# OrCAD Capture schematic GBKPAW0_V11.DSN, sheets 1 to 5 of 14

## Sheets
1 PAGE07:LCD PORT: size B; title: GBKPAW0_V1.1; rev: 1.1; note: 研发部
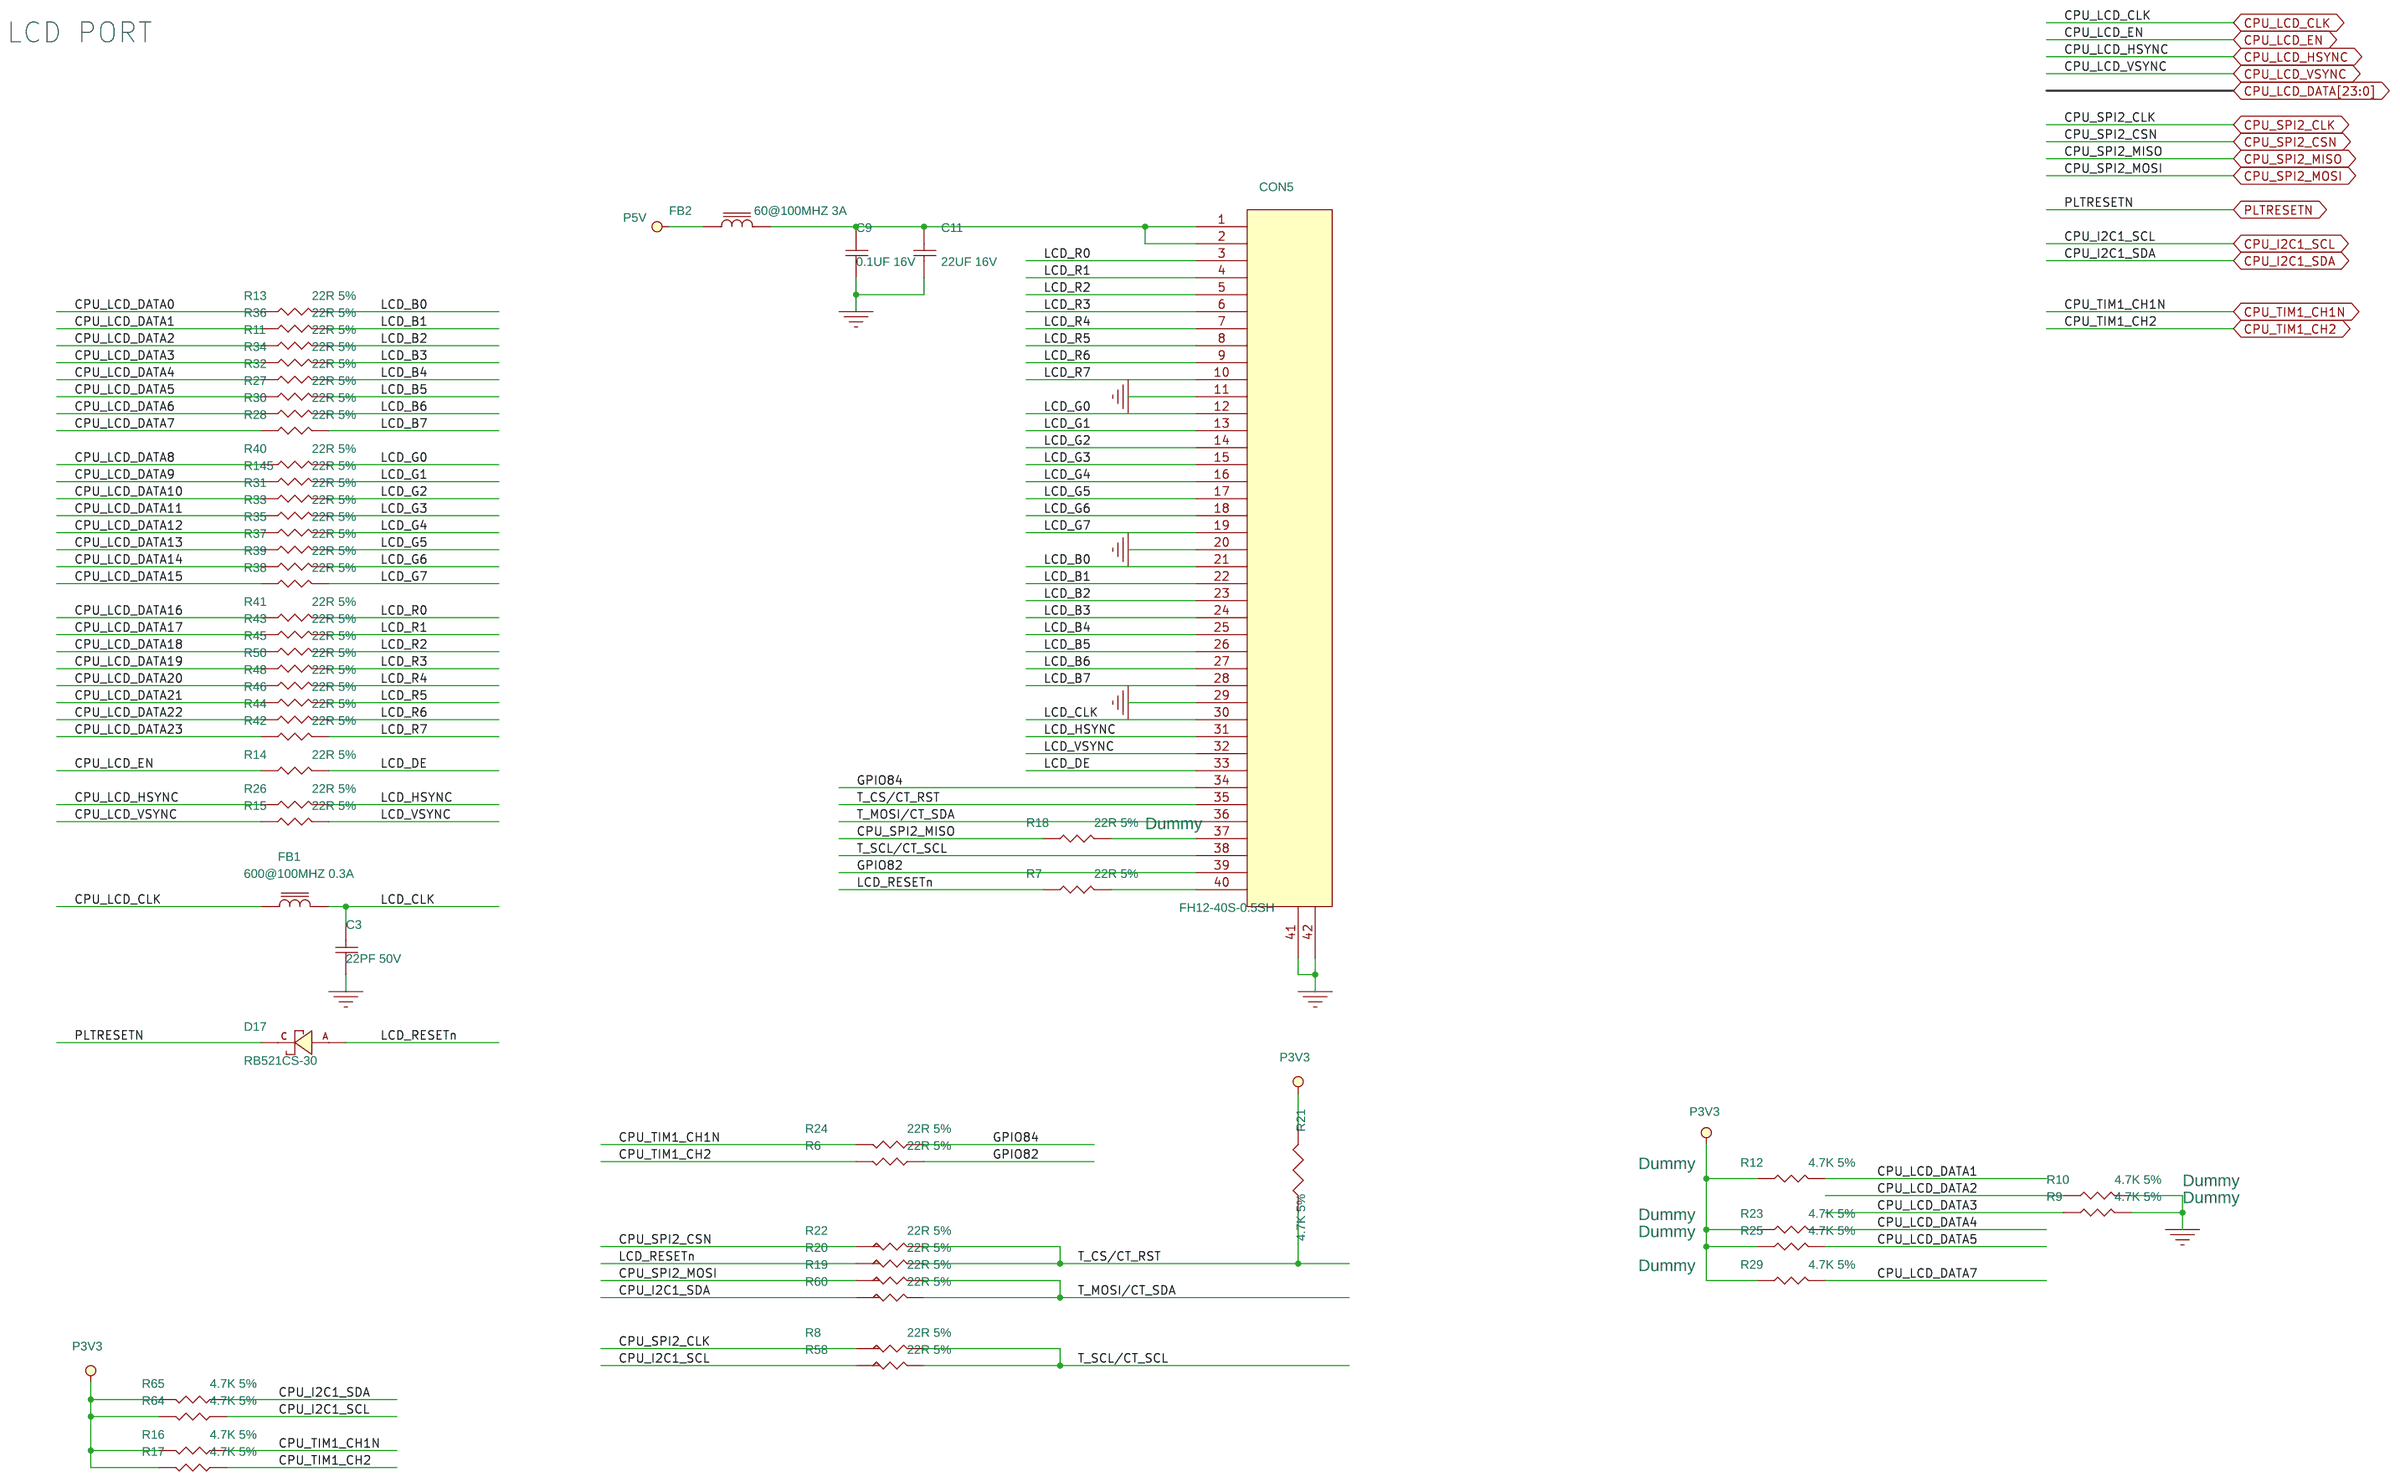
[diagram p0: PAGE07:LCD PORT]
2 PAGE13:P3V3: size B
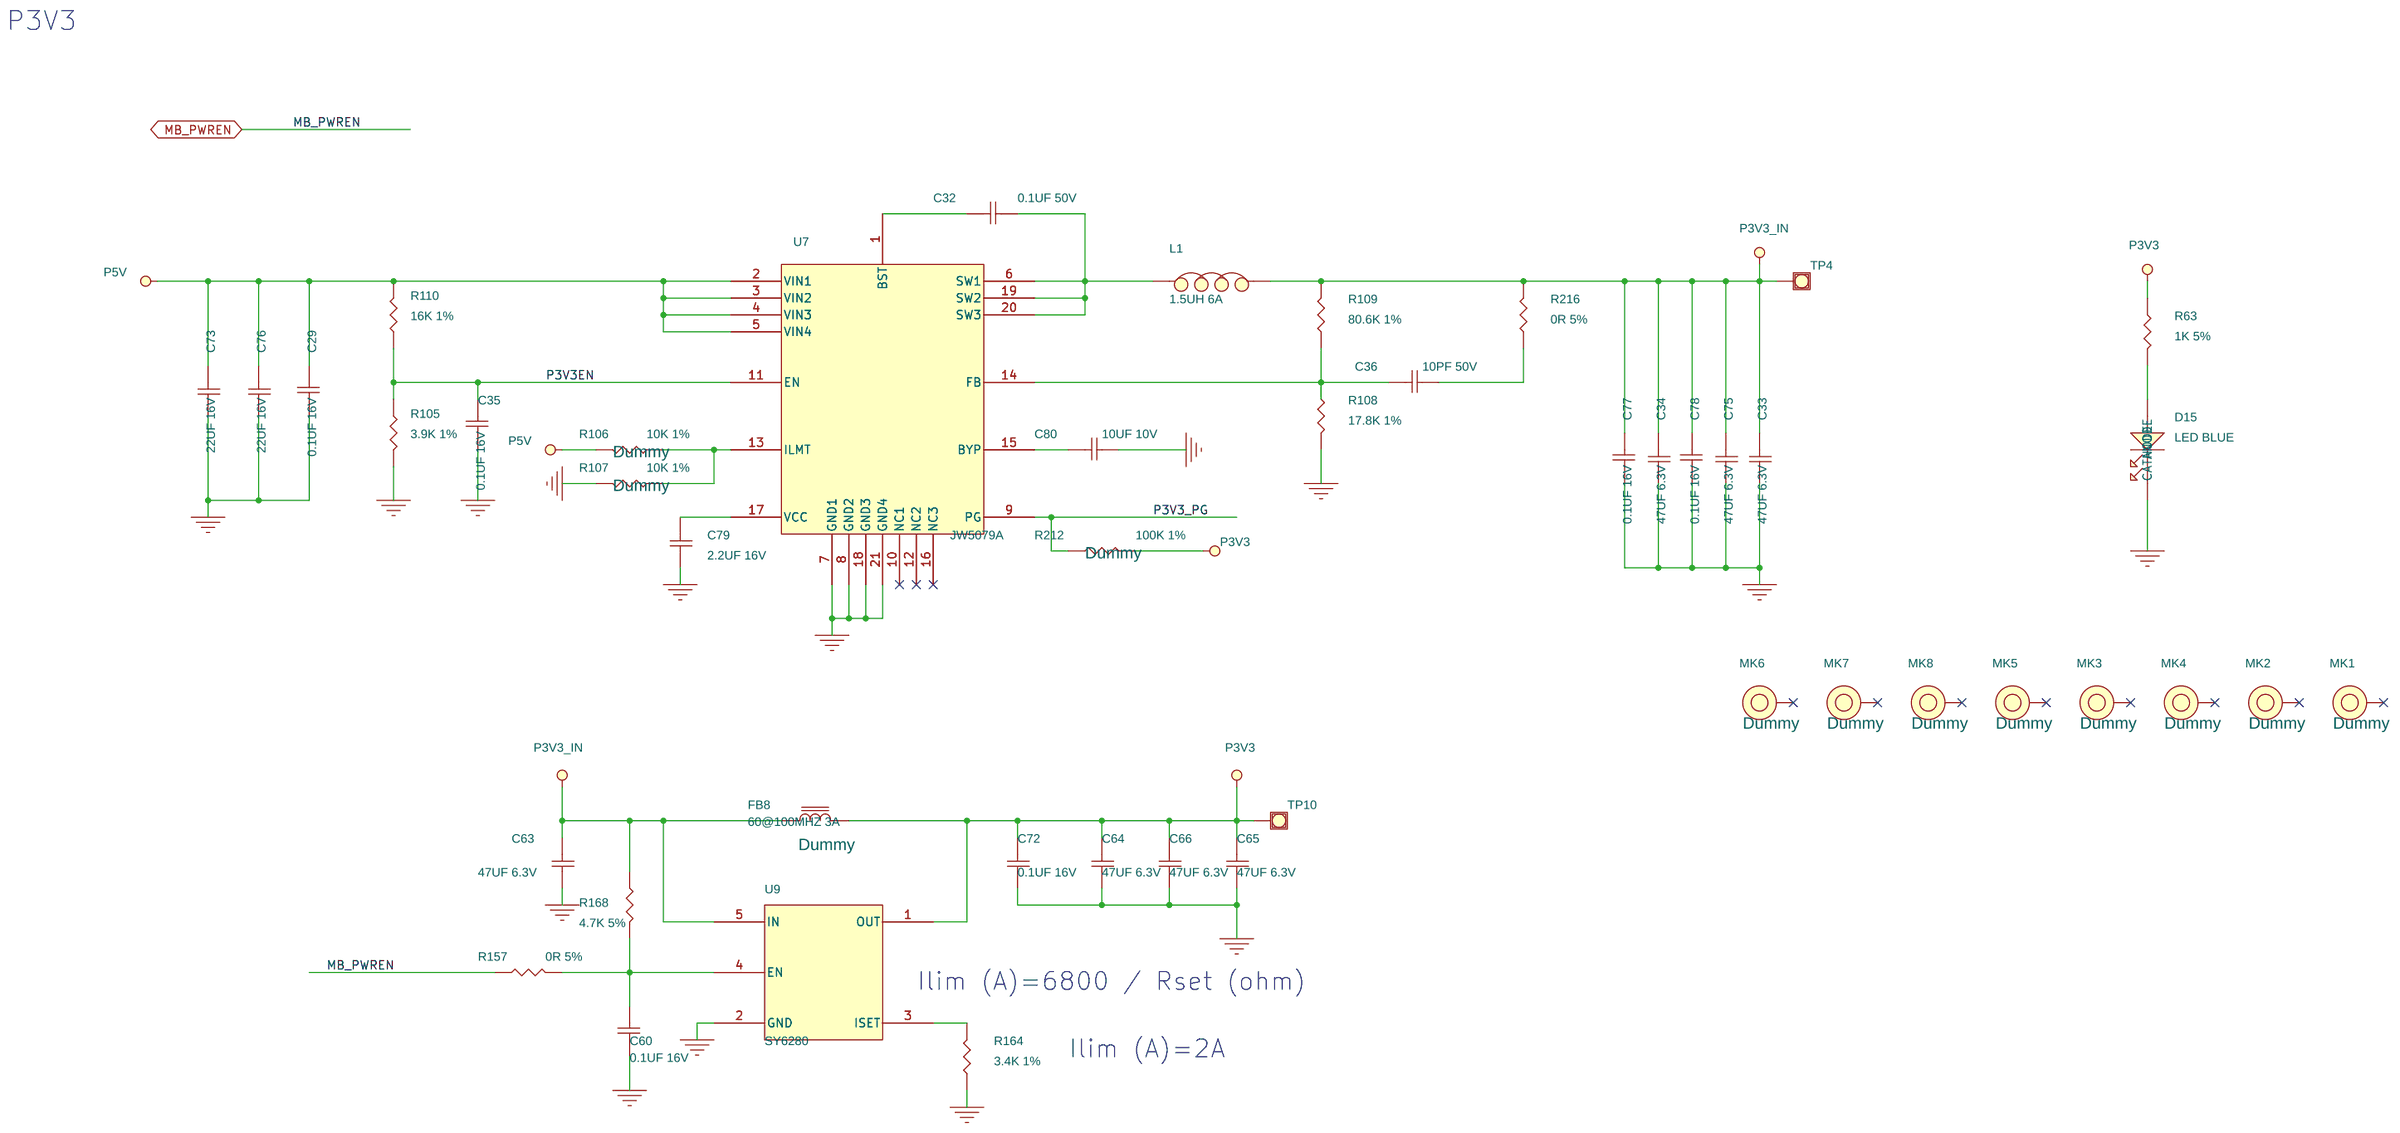
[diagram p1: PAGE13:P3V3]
3 PAGE05:USB: size B
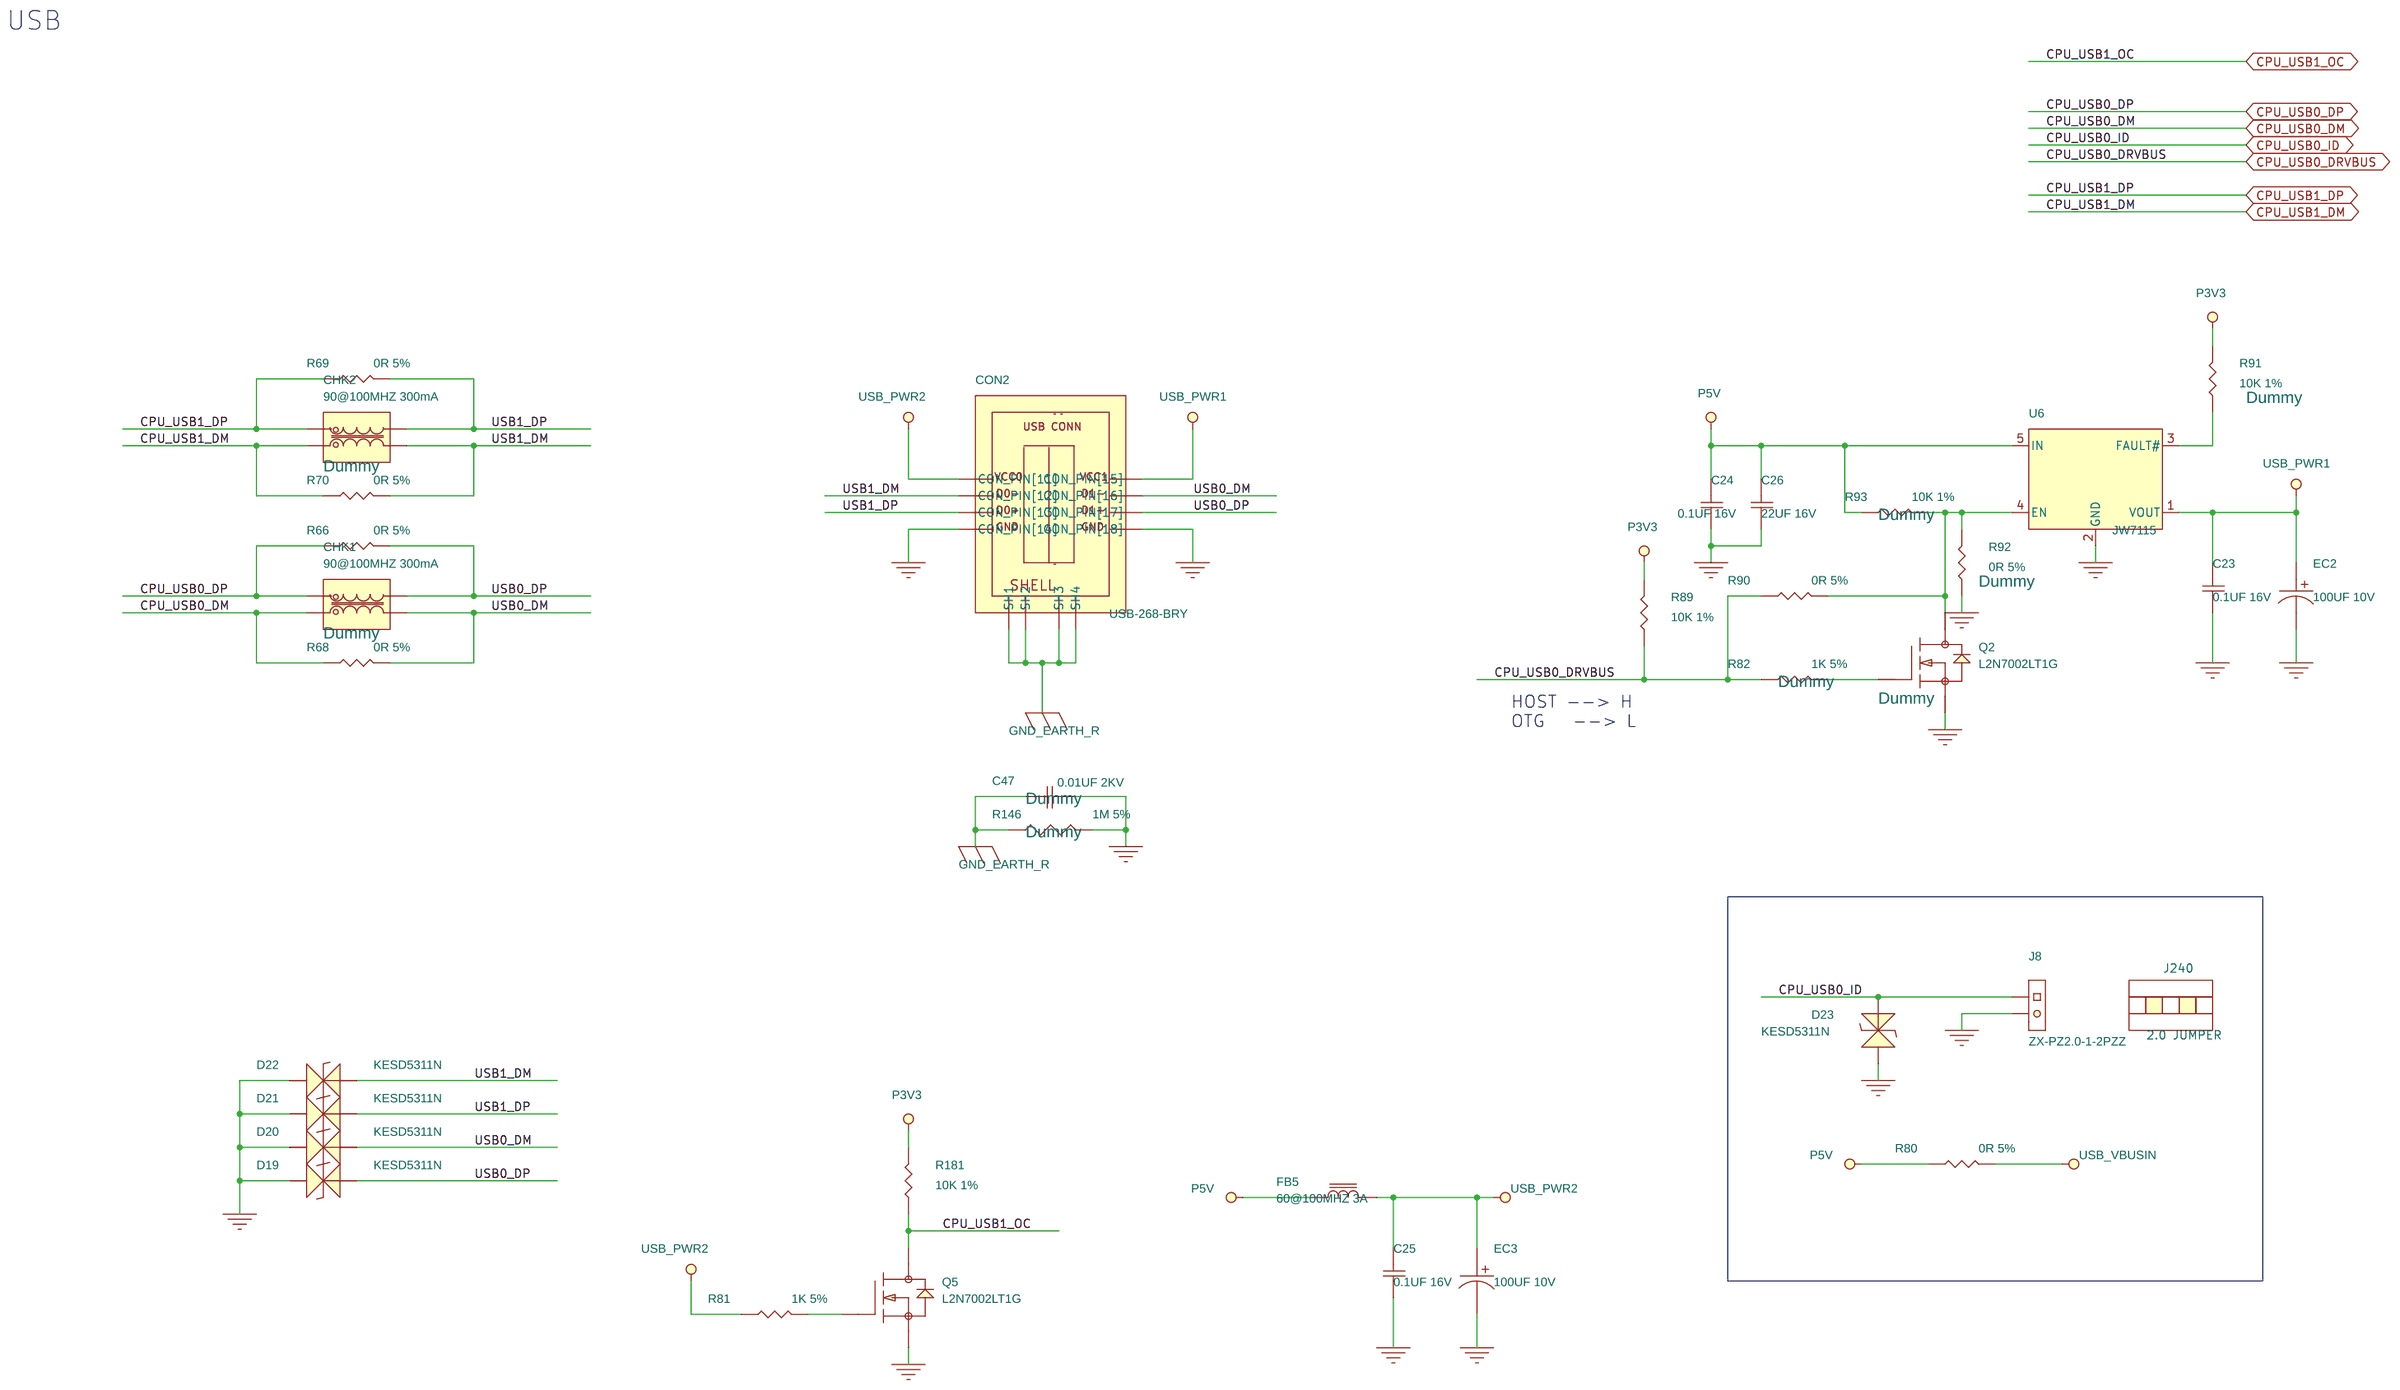
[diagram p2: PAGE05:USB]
4 PAGE09:AI&LAN: size B
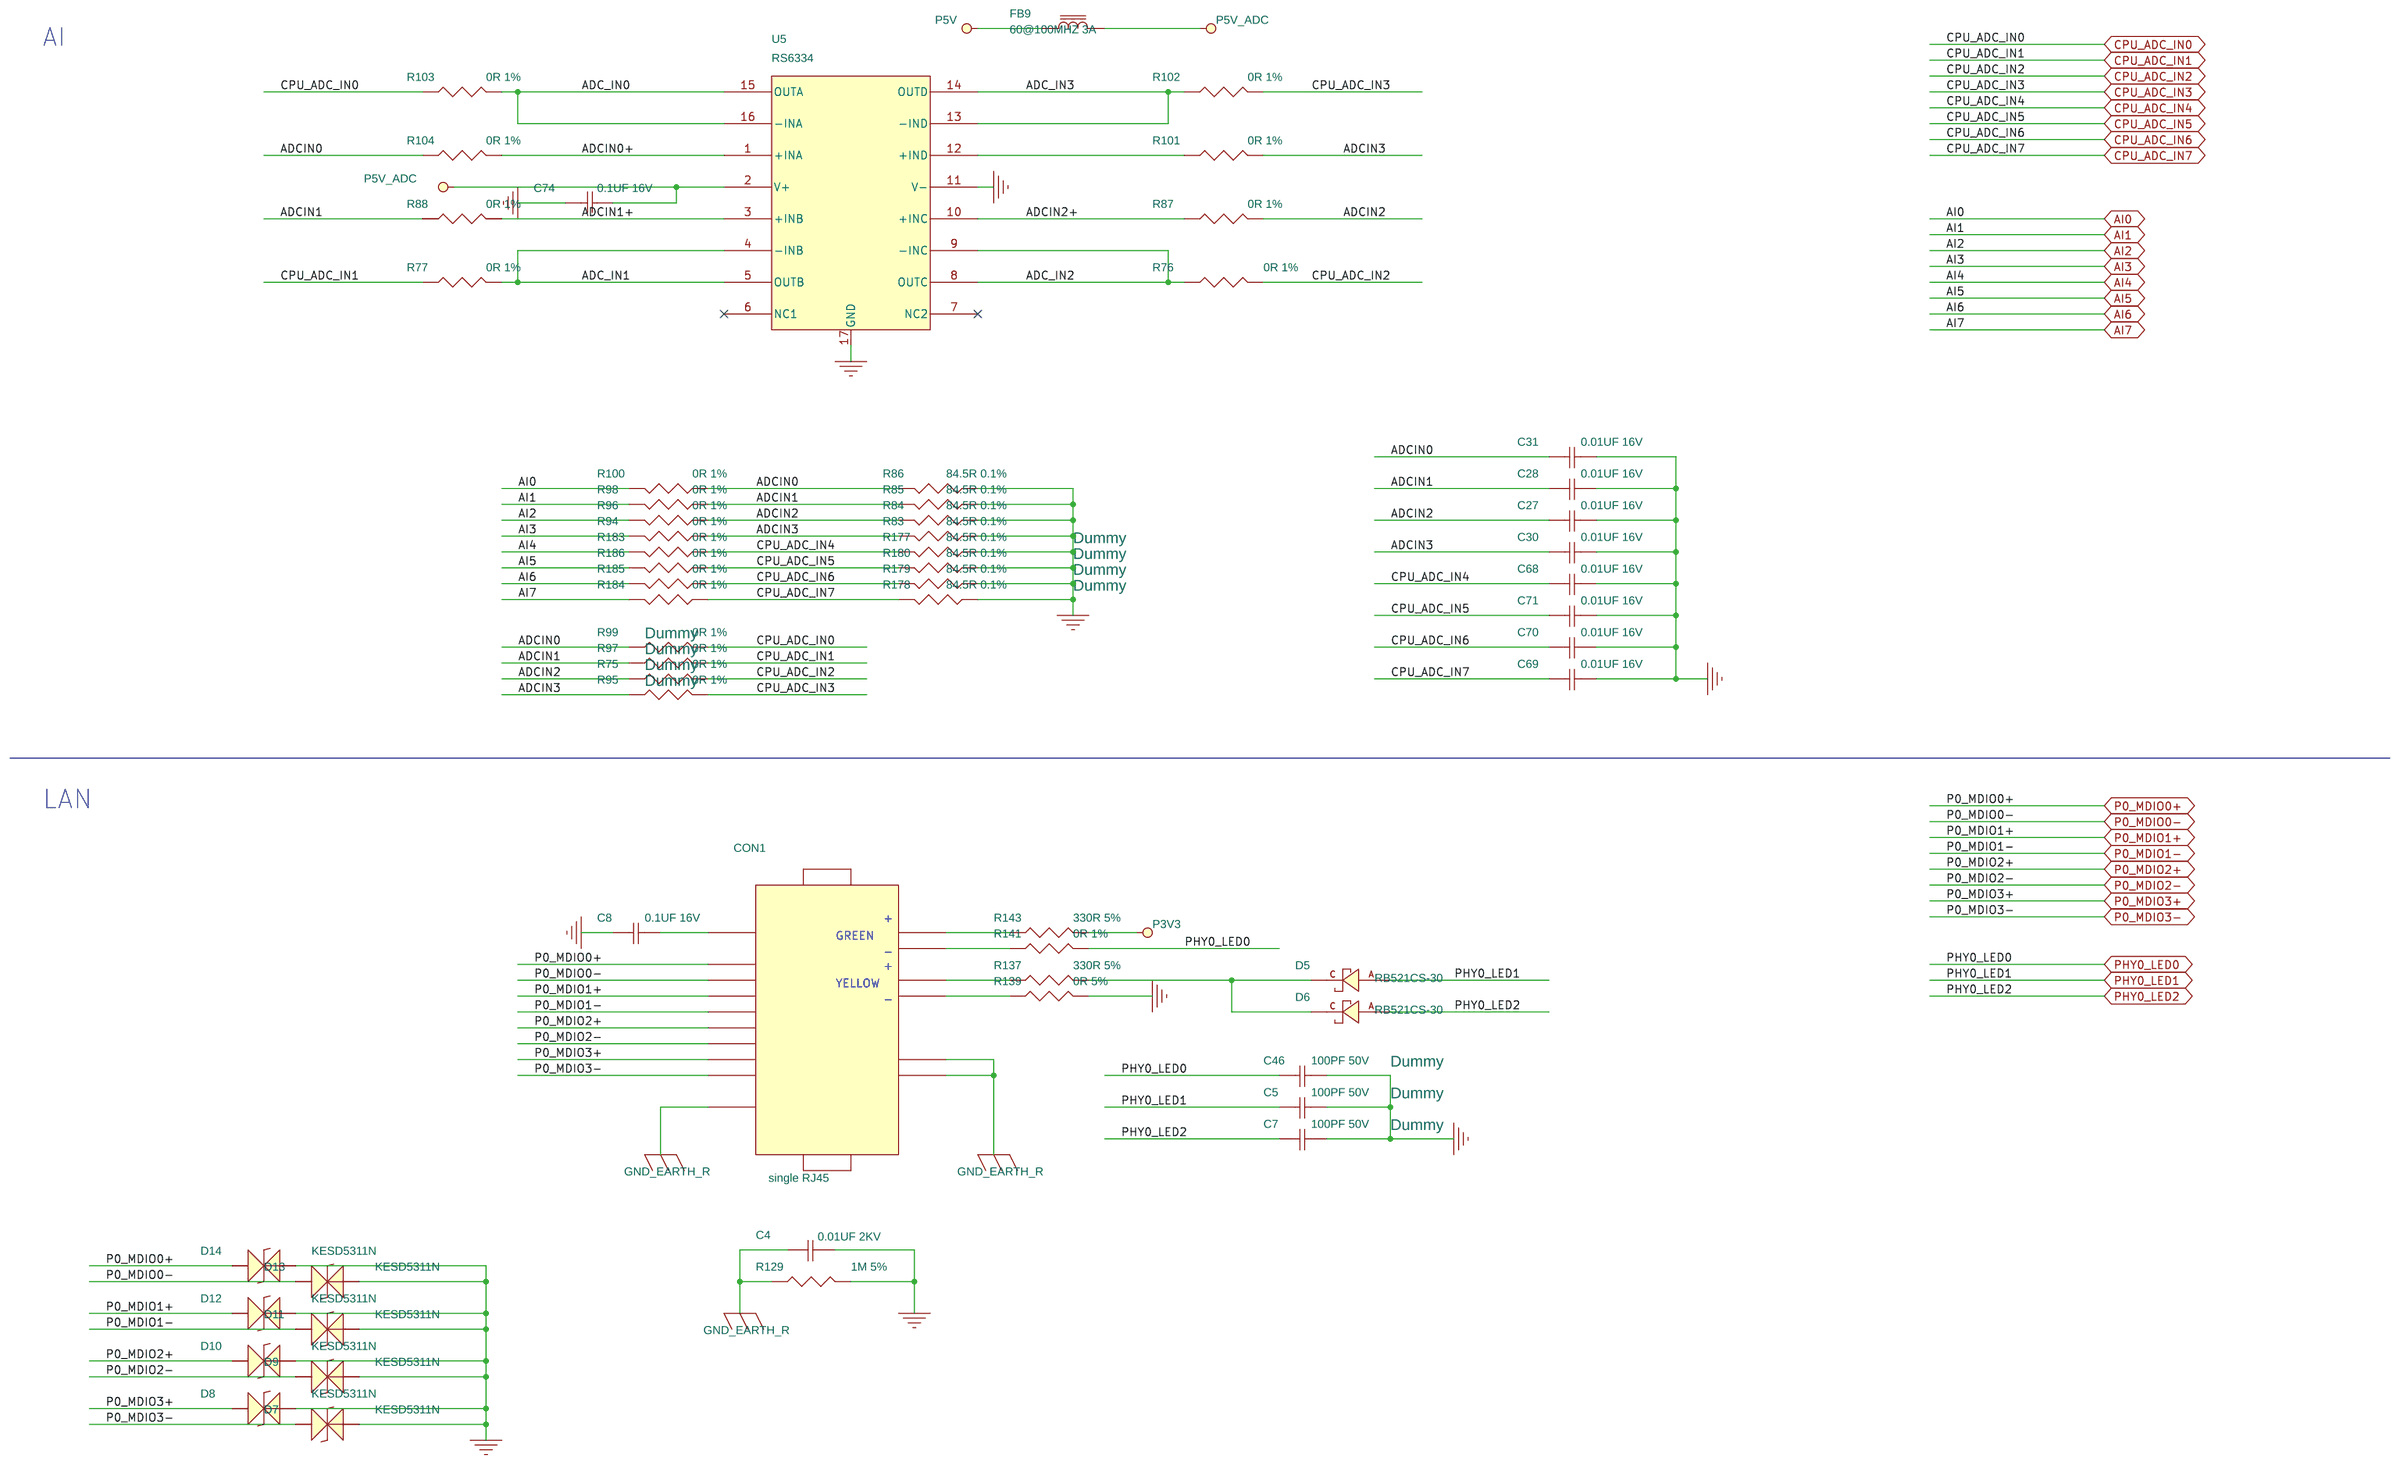
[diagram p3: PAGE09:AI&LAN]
5 PAGE01:COVER SHEET
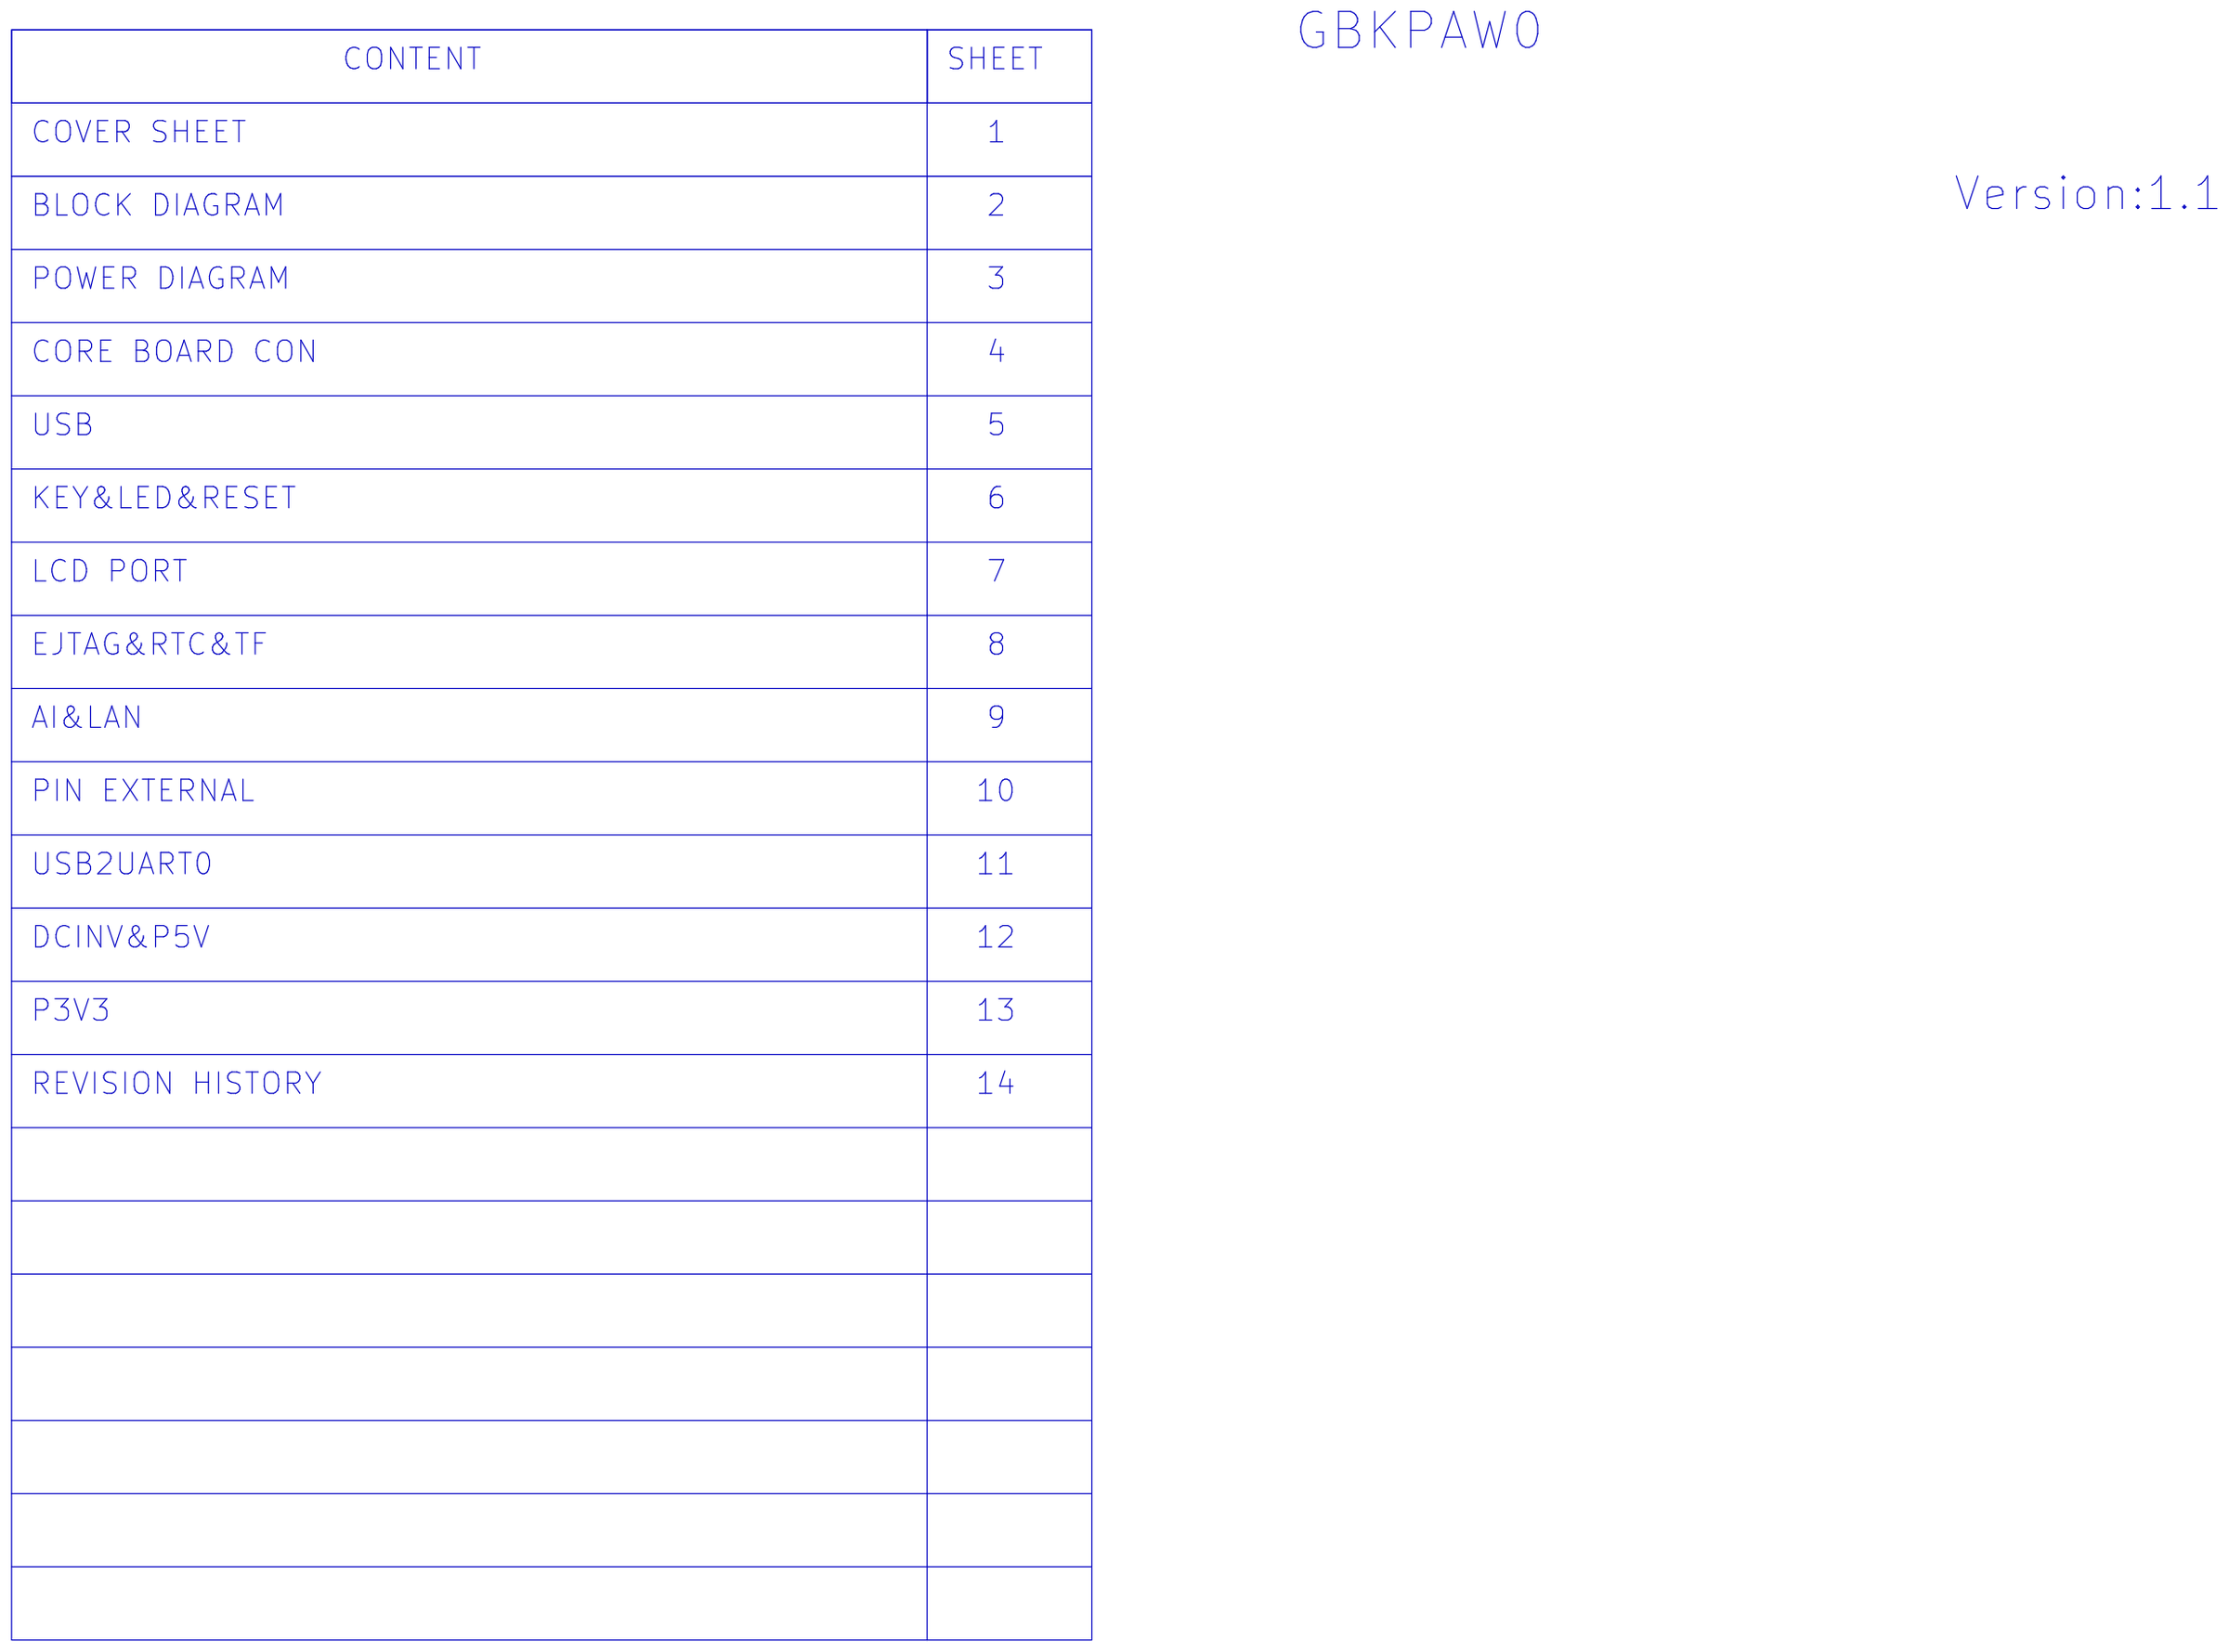
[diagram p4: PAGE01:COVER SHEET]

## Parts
sheet PAGE05:USB
C23  0.1UF 16V  [C0402]
C24  0.1UF 16V  [C0402]
C25  0.1UF 16V  [C0402]
C26  22UF 16V  [C0805]
C47  0.01UF 2KV  [C1206]
CHK1  90@100MHZ 300mA  [FB4-0805]
CHK2  90@100MHZ 300mA  [FB4-0805]
CON2  USB-268-BRY  [USB8-H-2X1_2]
D19  KESD5311N  [ESDPSA-0402]
D20  KESD5311N  [ESDPSA-0402]
D21  KESD5311N  [ESDPSA-0402]
D22  KESD5311N  [ESDPSA-0402]
D23  KESD5311N  [ESDPSA-0402]
EC2  100UF 10V  [TC3528-21]
EC3  100UF 10V  [TC3528-21]
FB5  60@100MHZ 3A  [FB0603]
J8  ZX-PZ2.0-1-2PZZ  [HEAD2-79]
J240  2.0 JUMPER
Q2  L2N7002LT1G  [SOT23-3]
Q5  L2N7002LT1G  [SOT23-3]
R66  0R 5%  [R0402]
R68  0R 5%  [R0402]
R69  0R 5%  [R0402]
R70  0R 5%  [R0402]
R80  0R 5%  [R0402]
R81  1K 5%  [R0402]
R82  1K 5%  [R0402]
R89  10K 1%  [R0402]
R90  0R 5%  [R0402]
R91  10K 1%  [R0402]
R92  0R 5%  [R0402]
R93  10K 1%  [R0402]
R146  1M 5%  [R0603]
R181  10K 1%  [R0402]
U6  JW7115  [SOT23-5]
sheet PAGE07:LCD PORT
C3  22PF 50V  [C0402]
C9  0.1UF 16V  [C0402]
C11  22UF 16V  [C0805]
CON5  FH12-40S-0.5SH  [FPC40-20]
D17  RB521CS-30  [DIODE_SOD923]
FB1  600@100MHZ 0.3A  [FB0402]
FB2  60@100MHZ 3A  [FB0603]
R6  22R 5%  [R0402]
R7  22R 5%  [R0402]
R8  22R 5%  [R0402]
R9  4.7K 5%  [R0402]
R10  4.7K 5%  [R0402]
R11  22R 5%  [R0402]
R12  4.7K 5%  [R0402]
R13  22R 5%  [R0402]
R14  22R 5%  [R0402]
R15  22R 5%  [R0402]
R16  4.7K 5%  [R0402]
R17  4.7K 5%  [R0402]
R18  22R 5%  [R0402]
R19  22R 5%  [R0402]
R20  22R 5%  [R0402]
R21  4.7K 5%  [R0402]
R22  22R 5%  [R0402]
R23  4.7K 5%  [R0402]
R24  22R 5%  [R0402]
R25  4.7K 5%  [R0402]
R26  22R 5%  [R0402]
R27  22R 5%  [R0402]
R28  22R 5%  [R0402]
R29  4.7K 5%  [R0402]
R30  22R 5%  [R0402]
R31  22R 5%  [R0402]
R32  22R 5%  [R0402]
R33  22R 5%  [R0402]
R34  22R 5%  [R0402]
R35  22R 5%  [R0402]
R36  22R 5%  [R0402]
R37  22R 5%  [R0402]
R38  22R 5%  [R0402]
R39  22R 5%  [R0402]
R40  22R 5%  [R0402]
R41  22R 5%  [R0402]
R42  22R 5%  [R0402]
R43  22R 5%  [R0402]
R44  22R 5%  [R0402]
R45  22R 5%  [R0402]
R46  22R 5%  [R0402]
R48  22R 5%  [R0402]
R50  22R 5%  [R0402]
R58  22R 5%  [R0402]
R60  22R 5%  [R0402]
R64  4.7K 5%  [R0402]
R65  4.7K 5%  [R0402]
R145  22R 5%  [R0402]
sheet PAGE09:AI&LAN
C4  0.01UF 2KV  [C1206]
C5  100PF 50V  [C0402]
C7  100PF 50V  [C0402]
C8  0.1UF 16V  [C0402]
C27  0.01UF 16V  [C0402]
C28  0.01UF 16V  [C0402]
C30  0.01UF 16V  [C0402]
C31  0.01UF 16V  [C0402]
C46  100PF 50V  [C0402]
C68  0.01UF 16V  [C0402]
C69  0.01UF 16V  [C0402]
C70  0.01UF 16V  [C0402]
C71  0.01UF 16V  [C0402]
C74  0.1UF 16V  [C0402]
CON1  single RJ45  [RJ45-10-100-LED2-M]
D5  RB521CS-30  [DIODE_SOD923]
D6  RB521CS-30  [DIODE_SOD923]
D7  KESD5311N  [ESDPSA-0402]
D8  KESD5311N  [ESDPSA-0402]
D9  KESD5311N  [ESDPSA-0402]
D10  KESD5311N  [ESDPSA-0402]
D11  KESD5311N  [ESDPSA-0402]
D12  KESD5311N  [ESDPSA-0402]
D13  KESD5311N  [ESDPSA-0402]
D14  KESD5311N  [ESDPSA-0402]
FB9  60@100MHZ 3A  [FB0603]
R75  0R 1%  [R0402]
R76  0R 1%  [R0402]
R77  0R 1%  [R0402]
R83  84.5R 0.1%  [R0603]
R84  84.5R 0.1%  [R0603]
R85  84.5R 0.1%  [R0603]
R86  84.5R 0.1%  [R0603]
R87  0R 1%  [R0402]
R88  0R 1%  [R0402]
R94  0R 1%  [R0402]
R95  0R 1%  [R0402]
R96  0R 1%  [R0402]
R97  0R 1%  [R0402]
R98  0R 1%  [R0402]
R99  0R 1%  [R0402]
R100  0R 1%  [R0402]
R101  0R 1%  [R0402]
R102  0R 1%  [R0402]
R103  0R 1%  [R0402]
R104  0R 1%  [R0402]
R129  1M 5%  [R0603]
R137  330R 5%  [R0402]
R139  0R 5%  [R0402]
R141  0R 1%  [R0402]
R143  330R 5%  [R0402]
R177  84.5R 0.1%  [R0603]
R178  84.5R 0.1%  [R0603]
R179  84.5R 0.1%  [R0603]
R180  84.5R 0.1%  [R0603]
R183  0R 1%  [R0402]
R184  0R 1%  [R0402]
R185  0R 1%  [R0402]
R186  0R 1%  [R0402]
U5  RS6334  [QFN16-050-3X3]
sheet PAGE13:P3V3
C29  0.1UF 16V  [C0402]
C32  0.1UF 50V  [C0603]
C33  47UF 6.3V  [C0805]
C34  47UF 6.3V  [C0805]
C35  0.1UF 16V  [C0402]
C36  10PF 50V  [C0402]
C60  0.1UF 16V  [C0402]
C63  47UF 6.3V  [C0805]
C64  47UF 6.3V  [C0805]
C65  47UF 6.3V  [C0805]
C66  47UF 6.3V  [C0805]
C72  0.1UF 16V  [C0402]
C73  22UF 16V  [C0805]
C75  47UF 6.3V  [C0805]
C76  22UF 16V  [C0805]
C77  0.1UF 16V  [C0402]
C78  0.1UF 16V  [C0402]
C79  2.2UF 16V  [C0603]
C80  10UF 10V  [C0603]
D15  LED BLUE  [LEDS_19_21SYGC]
FB8  60@100MHZ 3A  [FB0603]
L1  1.5UH 6A  [PL0504]
MK1  X_Mark Point  [ID-BOARD]
MK2  X_Mark Point  [ID-BOARD]
MK3  X_Mark Point  [ID-BOARD]
MK4  X_Mark Point  [ID-BOARD]
MK5  X_Mark Point  [ID-BOARD]
MK6  X_Mark Point  [ID-BOARD]
MK7  X_Mark Point  [ID-BOARD]
MK8  X_Mark Point  [ID-BOARD]
R63  1K 5%  [R0402]
R105  3.9K 1%  [R0402]
R106  10K 1%  [R0402]
R107  10K 1%  [R0402]
R108  17.8K 1%  [R0402]
R109  80.6K 1%  [R0402]
R110  16K 1%  [R0402]
R157  0R 5%  [R0402]
R164  3.4K 1%  [R0402]
R168  4.7K 5%  [R0402]
R212  100K 1%  [R0402]
R216  0R 5%  [R0402]
TP4  X_SD_TSTR  [TP-SMD]
TP10  X_SD_TSTR  [TP-SMD]
U7  JW5079A  [QFN3X3_20]
U9  SY6280  [SOT23-5]

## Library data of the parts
C8 C23-C25 C29 C35 C60 C72 C77 C78 = C: CAP,MLCC,0.1UF,16V,10%,C0402/SMT,X7R,ROHS; Component Name: 0.1UF 16V C0402 YAGEO CC0402KRX7R7BB104; ID: 22; Manufacturer: YAGEO; Manufacturer PN: CC0402KRX7R7BB104; Option: I; Package type: SMT; Part Number: C111042XK62YG1; Part Type: 陶瓷电容; ROHS: Y; Remark: Reserved; Status: 商业级; Datasheet: D:\lib_ls\Datasheet\RC\YAGEO-C.pdf
C11 C26 C73 C76 = C: CAP,MLCC,22UF,16V,10%,C0805/SMT,X5R,ROHS; Component Name: 22UF 16V C0805 SAMSUNG CL21A226MOQNNNE; ID: 567; Manufacturer: SAMSUNG(三星); Manufacturer PN: CL21A226MOQNNNE; Option: I; Package type: SMT; Part Number: C1122645K62SA1-GZ; Part Type: 陶瓷电容; ROHS: Y; Remark: Reserved; Status: 商业级; Datasheet: D:\lib_ls\Datasheet\RC\CL21A226MOQNNNE.PDF
C47 = C: CAP,MLCC,0.01UF,2KV,10%,C1206/SMT,X7R,ROHS; Component Name: 0.01UF 2KV C1206 FH 1206B103K202NT; ID: 504; Manufacturer: FH(风华); Manufacturer PN: 1206B103K202NT; Option: I; Package type: SMT; Part: 0.01UF 2KV  NC; Part Number: C111036XKM2FH1-GZ; Part Type: 陶瓷电容; ROHS: Y; Remark: Dummy; Status: 商业级; Datasheet: D:\lib_ls\Datasheet\RC\FH-C.pdf
CHK1 = CHOCK: IND FERRITE BEAD, 90 Ohm, ±25%, FB4-0805/SMT, 0.3A, 0.3 Ohm, ROHS; Component Name: 90@100MHZ 300mA ACM2012D-900-2P-T00; Manufacturer: TDK; Manufacturer PN: ACM2012D-900-2P-T00; Option: I; Package type: SMT; Part Number: LFB90041Y62TD1; Part Type: 磁珠; ROHS: Y; Remark: Dummy; SIGNAL_MODEL: CHOCK_FB4-0805_90@100MHZ_300MA; Status: 商业级; Temperature: Ta=-25 to +85; Datasheet: Z:\lib\Datasheet\Inductor-Bead\ACM2012D-900-2P-T00.pdf
CHK2 = CHOCK: IND FERRITE BEAD, 90 Ohm, ±25%, FB4-0805/SMT, 0.3A, 0.3 Ohm, ROHS; Component Name: 90@100MHZ 300mA ACM2012D-900-2P-T00; Manufacturer: TDK; Manufacturer PN: ACM2012D-900-2P-T00; Option: I; Package type: SMT; Part Number: LFB90041Y62TD1; Part Type: 磁珠; ROHS: Y; Remark: Dummy; SIGNAL_MODEL: CHOCK_FB4-0805_90@100MHZ_300MA_90@100MHZ_300mA; Status: 商业级; Temperature: Ta=-25 to +85; Datasheet: Z:\lib\Datasheet\Inductor-Bead\ACM2012D-900-2P-T00.pdf
CON2 = J02UB1112C2FC1: CNT dual USB,TypeA,USB2.0,12pin/DIP,Horizon,ROHS; Component Name: CNT dual USB,TypeA,USB2.0,12pin/DIP,Horizon,ROHS; ID: 573; Manufacturer: XUNPU(讯普); Option: I; Part Number: J02UB268BC1XP1-GZ; Part Type: 接插件    USB; ROHS: Y; Remark: Reserved; Status: 商业级; Datasheet: D:\lib_ls\Datasheet\connector\02\USB-268-BRY.pdf
D19-D23 = ESD_DIODE_0: ESD Protection devices,ESDPSA-0402/SMT,ESD protection for high speed data lines,ROHS; Component Name: KUU KESD5311N; ID: 160; Manufacturer: KUU; Option: I; Package type: SMT; Part Number: DJ1ESDPSA12SKU-GZ; Part Type: 瞬态电压抑制二极管; ROHS: Y; Remark: Reserved; Status: 商业级; Datasheet: D:\lib_ls\Datasheet\KESD5311N.PDF
EC2 EC3 = CT: CAP,钽电容,100UF,10V,20%,TC3528-21/SMT,ROHS; Component Name: 22UF 16V TC3528-21 KEMET T491B226K016AT; ID: 194; Manufacturer: Sunlord(顺络); Manufacturer PN: TC212B107M010B; Option: I; Package type: SMT; Part Type: 钽电容; ROHS: Y; Remark: Reserved; Status: 商业级
FB2 FB5 FB9 = BEAD: IND FERRITE BEAD, 60 Ohm, ±25%, FB0603/SMT, 3A, 0.04 Ohm, ROHS; Component Name: 60@100MHZ 3A PBY160808T-600Y-N; Manufacturer: CHILISIN; Manufacturer PN: PBY160808T-600Y-N; Option: I; Package type: SMT; Part Number: LFB60031YF2CN1; Part Type: 磁珠; ROHS: Y; Remark: Reserved; Status: 商业级; Datasheet: D:\lib\Datasheet\Inductor-Bead\PBY160808T-600Y-N.pdf
J8 = 2_00_0: CNT Single HEADER, 2_00_1X2PIN, Megastar/ZX-PZ2.0-1-2PZZ, HEAD2-79/DIP, 2.00mm, Black, Vertical,ROHS; Component Name: CNT Single HEADER, 2_00_1X2PIN, Megastar/ZX-PZ2.0-1-2PZZ, HEAD2-79/DIP, 2.00mm, Black, Vertical,ROHS; ID: 564; Manufacturer: Megastar(兆星); Option: I; Part Number: J262001X021ME1; Part Type: 接插件    PIN HEADER; ROHS: /; Remark: 间距:2mm 1x2P 直插 方针; Status: 商业级; Datasheet: D:\lib_ls\Datasheet\Connector\26\排针_ZX-PZ2.0-1-2PZZ.PDF
J240 = MINI_JUMPER: CNT MINI JUMPER, 2 PIN,2mm, BLACK,Ta=-40 to +85, Unknown ROHS; Component Name: CNT MINI JUMPER, 2 PIN,2mm, BLACK,Ta=-40 to +85, Unknown ROHS    BOOMELE/2.0 MINI JUMPER; ID: 523; Manufacturer: BOOMELE(博穆精密); Manufacturer PN: 2.0JUMPER; Option: I; Package type: DIP; Part Number: J3220MINI11EC1-GZ; Part Type: 接插件    跳线帽; ROHS: /; Status: 商业级; Datasheet: D:\lib_ls\Datasheet\connector\32\C5664_2MM开顶式.pdf
Q2 = L2N7002LT1G: IC MOSFET, LRC/L2N7002LT1G, SOT23-3/SMT, 60 V 115 mA N-Channel SOT-23, ROHS; Component Name: LRC    L2N7002LT1G; Manufacturer: LRC; Option: I; Package type: SMT; Part Number: US12N700232QT1; Part Type: IC/N-Channel; ROHS: Y; Remark: Dummy; Reserved: TOP-SIDE MARKING：702；广州龙芯料号GQM114011132L041，与2N7002LT1G互为替代料，但2N7002LT1G的起订量太大，现使用L2N7002LT1G; Status: U; Temperature: Tj=-55 to +150; Datasheet: Z:\lib\Datasheet\IC\L2N7002LT1G.pdf
Q5 = L2N7002LT1G: IC MOSFET, LRC/L2N7002LT1G, SOT23-3/SMT, 60 V 115 mA N-Channel SOT-23, ROHS; Component Name: LRC    L2N7002LT1G; Manufacturer: LRC; Option: I; Package type: SMT; Part Number: US12N700232QT1; Part Type: IC/N-Channel; ROHS: Y; Remark: Reserved; Reserved: TOP-SIDE MARKING：702；广州龙芯料号GQM114011132L041，与2N7002LT1G互为替代料，但2N7002LT1G的起订量太大，现使用L2N7002LT1G; Status: U; Temperature: Tj=-55 to +150; Datasheet: Z:\lib\Datasheet\IC\L2N7002LT1G.pdf
R66 R68-R70 = R_v5: RESISITOR, 0R Ohm, 5%, R0402/SMT, 1/16W, ROHS; Component Name: 0R 5% R0402 FH RC-02000JT; ID: 1,250; Manufacturer: FH(风华); Manufacturer PN: RC-02000JT; Option: I; Package type: SMT; Part Number: R1100002JC2FH1-GZ; Part Type: 电阻; ROHS: Y; Remark: Reserved; SIGNAL_MODEL: R_R0402_0R_5%; Status: 商业级; Datasheet: D:\lib_ls\Datasheet\RC\FH-R.pdf
R80 R90 R157 R216 = R_v5: RESISITOR, 0R Ohm, 5%, R0402/SMT, 1/16W, ROHS; Component Name: 0R 5% R0402 FH RC-02000JT; ID: 1,250; Manufacturer: FH(风华); Manufacturer PN: RC-02000JT; Option: I; Package type: SMT; Part Number: R1100002JC2FH1-GZ; Part Type: 电阻; ROHS: Y; Remark: Reserved; Status: 商业级; Datasheet: D:\lib_ls\Datasheet\RC\FH-R.pdf
R81 = R_v5: RESISITOR, 1K Ohm, 5%, R0402/SMT, 1/16W, ROHS; Component Name: 1K 5% R0402 YAGEO RC0402JR-071KL; ID: 18; Manufacturer: YAGEO; Manufacturer PN: RC0402JR-071KL; Option: I; Part Number: R1101022JC2YG1; Part Type: 电阻; ROHS: Y; Remark: Reserved; Status: 商业级; Datasheet: D:\lib_ls\Datasheet\RC\YAGEO-R.pdf
R82 = R_v5: RESISITOR, 1K Ohm, 5%, R0402/SMT, 1/16W, ROHS; Component Name: 1K 5% R0402 YAGEO RC0402JR-071KL; ID: 18; Manufacturer: YAGEO; Manufacturer PN: RC0402JR-071KL; Option: I; Part Number: R1101022JC2YG1; Part Type: 电阻; ROHS: Y; Remark: Dummy; Status: 商业级; Datasheet: D:\lib_ls\Datasheet\RC\YAGEO-R.pdf
R89 R181 = R_v5: RESISITOR, 10K Ohm, 1%, R0402/SMT, 1/16W, ROHS; Component Name: 10K 1% R0402 FH RC-02W1002FT; ID: 1,170; Manufacturer: FH(风华); Manufacturer PN: RC-02W1002FT; Option: I; Package type: SMT; Part Number: R1110022FC2FH1-GZ; Part Type: 电阻; ROHS: Y; Remark: Reserved; Status: 商业级; Datasheet: D:\lib_ls\Datasheet\RC\FH-R.pdf
R91 R93 R106 R107 = R_v5: RESISITOR, 10K Ohm, 1%, R0402/SMT, 1/16W, ROHS; Component Name: 10K 1% R0402 FH RC-02W1002FT; ID: 1,170; Manufacturer: FH(风华); Manufacturer PN: RC-02W1002FT; Option: I; Package type: SMT; Part Number: R1110022FC2FH1-GZ; Part Type: 电阻; ROHS: Y; Remark: Dummy; Status: 商业级; Datasheet: D:\lib_ls\Datasheet\RC\FH-R.pdf
R92 = R_v5: RESISITOR, 0R Ohm, 5%, R0402/SMT, 1/16W, ROHS; Component Name: 0R 5% R0402 FH RC-02000JT; ID: 1,250; Manufacturer: FH(风华); Manufacturer PN: RC-02000JT; Option: I; Package type: SMT; Part Number: R1100002JC2FH1-GZ; Part Type: 电阻; ROHS: Y; Remark: Dummy; Status: 商业级; Datasheet: D:\lib_ls\Datasheet\RC\FH-R.pdf
R146 = R: RESISITOR, 1M Ohm, 5%, R0603/SMT, 1/10W, ROHS; Component Name: 1M 5% R0603 TORCH RC0603-105J-T; ID: 29; Manufacturer: TORCH; Manufacturer PN: RC0603-105J-T; Option: I; Package type: SMT; Part Number: R1101053JC2TO1; Part Type: 电阻; ROHS: Y; Remark: Dummy; Status: 商业级; Datasheet: D:\lib_ls\Datasheet\RC\TORCH-R.pdf
U6 = SGM2588: IC LOAD SWITCH,Joulwatt/JW7115S-1SOTA#TRPBF,SOT23-5/SMT,Ultra-Low On-Resistance,1.3A,Soft Start,2.7V-5.5V,ROHS; ID: 1,105; Manufacturer: Joulwatt(杰华特); Manufacturer PN: JW7115S-1SOTA#TRPBF; Option: I; Package type: SMT; Part Number: UZ1JW7115H3JW1-GZ; Part Type: IC/Others; ROHS: Y; Remark: Active High,1.3A; Status: 工业级; Datasheet: D:\lib_ls\Datasheet\JW7115.pdf
C3 = C: CAP,MLCC,22PF,50V,5%,C0402/SMT,NPO,ROHS; Component Name: 22PF 50V C0402 YAGEO C0402JRNPO9BN220; Manufacturer: YAGEO; Manufacturer PN: C0402JRNPO9BN220; Option: I; Package type: SMT; Part Number: C112202NJA2YG1; Part Type: 陶瓷电容; ROHS: Y; Remark: Reserved; Status: 商业级; Datasheet: Z:\lib\Datasheet\RC\YAGEO-C.pdf
C9 = C: CAP,MLCC,0.1UF,16V,10%,C0402/SMT,X7R,ROHS; Component Name: 0.1UF 16V C0402 YAGEO CC0402KRX7R7BB104; Manufacturer: YAGEO; Manufacturer PN: CC0402KRX7R7BB104; Option: I; Package type: SMT; Part Number: C111042XK62YG1; Part Type: 陶瓷电容; ROHS: Y; Remark: Reserved; Status: U; Datasheet: Z:\lib\Datasheet\RC\YAGEO-C.pdf
CON5 = J1812400511HI1_0: CNT FPC Connector，40pin/SMT,0.5mm，FPC Connector; Component Name: FPC Connector FH12-40S-0.5SH; ID: 110; Manufacturer: HIROSE; Option: I; Package type: SMT; Part Number: J1812400511HI1; Part Type: 接插件    FPC; ROHS: /; Remark: Reserved; Status: 商业级; Datasheet: D:\lib_ls\Datasheet\connector\18\J1812400511HI1.pdf
D5 D6 D17 = DIODE_SCHOTTKY_AC: DIODE, SOD923/SMT, ,VR = 30V,IF = 200mA, ROHS; Component Name: TECH PUBLIC(台舟) RB521CS-30; ID: 161; Manufacturer: TECH PUBLIC(台舟); Option: I; Package type: SMT; Part Number: D11RB521CS30J1-GZ; Part Type: 二极管; ROHS: Y; Remark: Reserved; Status: 商业级; Datasheet: D:\lib_ls\Datasheet\Diodes-Transistor\RB521CS-30.pdf
FB1 = BEAD: IND FERRITE BEAD,  600Ohm, ±25%, FB4020/SMT,03. A, 055. Ohm, ROHS; Component Name: 600@100MHZ 0.3A BK1005HS601-TV; Manufacturer: TAIYO; Manufacturer PN: BK1005HS601-TV; Option: I; Package type: SMT; Part Number: LFB42041YG2TU1; Part Type: 磁珠; ROHS: Y; Remark: Reserved; SIGNAL_MODEL: BEAD_FB0402_600@100MHZ_0.3A; Status: 商业级; Temperature: Ta=-40 to +85; Datasheet: Z:\lib\Datasheet\Inductor-Bead\MJ2125HS420-T.pdf
R6 R7 R24 = R_v5: RESISITOR,22R Ohm,5%,R0402/SMT, 1/16W,ROHS; Component Name: 22R 5% R0402 FH  RC-02W220JT; ID: 1,186; Manufacturer: FH(风华); Manufacturer PN: RC-02W220JT; Option: I; Package type: SMT; Part Number: RJ102202JC2FH1-GZ; Part Type: 电阻; ROHS: Y; Remark: Reserved; Status: 商业级; Datasheet: D:\lib_ls\Datasheet\RC\FH-R.pdf
R8 R19 R22 = R_v6: RESISITOR,22R Ohm,5%,R0402/SMT, 1/16W,ROHS; APPROVED: 1-³ÐÕJ,ÓÐPDF™n; ASM_CFG: _; ASM_COMM: 5010; ASM_LVL: _; AVL_CFG: _; CFG_MSI: _; Component Name: 22R 5% R0402 FH  RC-02W220JT; GREEN_TYPE: 7-HE ŸoûuËØ&šWÃËÅÅÍâ—l¿î; ID: 1,186; MOD: _; Manufacturer: FH(风华); Manufacturer PN: RC-02W220JT; NEW_DESCRIPTION: ,RESISTOR,22Ohm,1%,1/16W,0402,HALOGEN FREE(EU EXEMPTION); Option: I; PART_NUMBER: R11-0220T12-W08; PART_TYPE: R; PCB_FOOTPRINT_N: N_R0402; Package type: SMT; Part Number: RJ102202JC2FH1-GZ; Part Type: 电阻; REMARK: Dummy; ROHS: Y; SIGNAL_MODEL: R_R0402_22R1%0402_R11-0220T12-W_22R1%0402; Status: 商业级; VENDOR: WALSIN; VENDOR_PART_NO: WR04X22R0FTL; Datasheet: D:\lib_ls\Datasheet\RC\FH-R.pdf
R9 R10 R12 R23 R25 R29 = R_v5: RESISITOR, 4.7K Ohm, 5%, R0402/SMT, 1/16W, ROHS; Component Name: 4.7K 5% R0402 FH RC-02W472JT; ID: 1,195; Manufacturer: FH(风华); Manufacturer PN: RC-02W472JT; Option: I; Package type: SMT; Part Number: R1104722JC2FH1-GZ; Part Type: 电阻; ROHS: Y; Remark: Dummy; Status: 商业级; Datasheet: D:\lib_ls\Datasheet\RC\FH-R.pdf
R11 R13-R15 R26-R28 R30-R46 R48 R50 R145 = R_v5: RESISITOR,22R Ohm,5%,R0402/SMT, 1/16W,ROHS; Component Name: 22R 5% R0402 FH  RC-02W220JT; ID: 1,186; Manufacturer: FH(风华); Manufacturer PN: RC-02W220JT; Option: I; Package type: SMT; Part Number: RJ102202JC2FH1-GZ; Part Type: 电阻; ROHS: Y; Remark: Reserved; SIGNAL_MODEL: R_R0402_0R_5%_0R_5%; Status: 商业级; Datasheet: D:\lib_ls\Datasheet\RC\FH-R.pdf
R16 R17 R168 = R_v5: RESISITOR, 4.7K Ohm, 5%, R0402/SMT, 1/16W, ROHS; Component Name: 4.7K 5% R0402 FH RC-02W472JT; ID: 1,195; Manufacturer: FH(风华); Manufacturer PN: RC-02W472JT; Option: I; Package type: SMT; Part Number: R1104722JC2FH1-GZ; Part Type: 电阻; ROHS: Y; Remark: Reserved; Status: 商业级; Datasheet: D:\lib_ls\Datasheet\RC\FH-R.pdf
R18 = R_v5: RESISITOR,22R Ohm,5%,R0402/SMT, 1/16W,ROHS; Component Name: 22R 5% R0402 FH  RC-02W220JT; ID: 1,186; Manufacturer: FH(风华); Manufacturer PN: RC-02W220JT; Option: I; Package type: SMT; Part Number: RJ102202JC2FH1-GZ; Part Type: 电阻; ROHS: Y; Remark: Dummy; Status: 商业级; Datasheet: D:\lib_ls\Datasheet\RC\FH-R.pdf
R20 R58 R60 = R_v6: RESISITOR,22R Ohm,5%,R0402/SMT, 1/16W,ROHS; APPROVED: 1-³ÐÕJ,ÓÐPDF™n; ASM_CFG: _; ASM_COMM: 5010; ASM_LVL: _; AVL_CFG: _; CFG_MSI: _; Component Name: 22R 5% R0402 FH  RC-02W220JT; GREEN_TYPE: 7-HE ŸoûuËØ&šWÃËÅÅÍâ—l¿î; ID: 1,186; MOD: _; Manufacturer: FH(风华); Manufacturer PN: RC-02W220JT; NEW_DESCRIPTION: ,RESISTOR,22Ohm,1%,1/16W,0402,HALOGEN FREE(EU EXEMPTION); Option: I; PART_NUMBER: R11-0220T12-W08; PART_TYPE: R; PCB_FOOTPRINT_N: N_R0402; Package type: SMT; Part Number: RJ102202JC2FH1-GZ; Part Type: 电阻; REMARK: Reserved; ROHS: Y; SIGNAL_MODEL: R_R0402_22R1%0402_R11-0220T12-W_22R1%0402; Status: 商业级; VENDOR: WALSIN; VENDOR_PART_NO: WR04X22R0FTL; Datasheet: D:\lib_ls\Datasheet\RC\FH-R.pdf
R21 = R: RESISITOR, 4.7K Ohm, 5%, R0402/SMT, 1/16W, ROHS; Component Name: 4.7K 5% R0402 FH RC-02W472JT; ID: 1,195; Manufacturer: FH(风华); Manufacturer PN: RC-02W472JT; Option: I; Package type: SMT; Part Number: R1104722JC2FH1-GZ; Part Type: 电阻; ROHS: Y; Remark: Reserved; Status: 商业级; Datasheet: D:\lib_ls\Datasheet\RC\FH-R.pdf
R64 R65 = R_v5: RESISITOR, 4.7K Ohm, 5%, R0402/SMT, 1/16W, ROHS; Component Name: 4.7K 5% R0402 FH RC-02W472JT; ID: 1,195; Manufacturer: FH(风华); Manufacturer PN: RC-02W472JT; Option: I; Package type: SMT; Part Number: R1104722JC2FH1-GZ; Part Type: 电阻; ROHS: Y; Remark: Reserved; SIGNAL_MODEL: R_R0402_4.7K_5%_4.7K_5%; Status: 商业级; Datasheet: D:\lib_ls\Datasheet\RC\FH-R.pdf
C4 = C: CAP,MLCC,0.01UF,2KV,10%,C1206/SMT,X7R,ROHS; Component Name: 0.01UF 2KV C1206 FH 1206B103K202NT; ID: 504; Manufacturer: FH(风华); Manufacturer PN: 1206B103K202NT; Option: I; Package type: SMT; Part: 0.01UF 2KV  NC; Part Number: C111036XKM2FH1-GZ; Part Type: 陶瓷电容; ROHS: Y; Remark: Reserved; Status: 商业级; Datasheet: D:\lib_ls\Datasheet\RC\FH-C.pdf
C5 C7 C46 = C: CAP,MLCC,100PF,50V,5%,C0402/SMT,CG,ROHS; Component Name: 100PF 50V C0402 TORCH CC41-0402-CG-50V-100P-J(N); Manufacturer: YAGEO; Manufacturer PN: C0402JRNPO9BN101; Option: I; Package type: SMT; Part Number: C111012NJA2YG1; Part Type: 陶瓷电容; ROHS: Y; Remark: Dummy; SIGNAL_MODEL: C_C0402_100PF50V_100PF_50V; Status: U; Datasheet: D:\Program Files\Cadence\lib\Datasheet\RC\TORCH-C.pdf
C27 C28 C30 C31 C68-C71 = C: CAP,MLCC,0.01UF,16V,10%,C0402/SMT,2X1,ROHS; Component Name: 0.01UF 16V C0402 TORCH CT41G-0402-2X1-16V-0.01UF-K(N); ID: 15; Manufacturer: TORCH; Manufacturer PN: CT41G-0402-2X1-16V-0.01UF-K(N); Option: I; Package type: SMT; Part Number: C111032XK62TO1; Part Type: 陶瓷电容; ROHS: Y; Remark: Reserved; Status: 商业级; Datasheet: D:\lib_ls\Datasheet\RC\TORCH-C.pdf
C74 = C: CAP,MLCC,0.1UF,16V,10%,C0402/SMT,X7R,ROHS; Component Name: 0.1UF 16V C0402 YAGEO CC0402KRX7R7BB104; Manufacturer: YAGEO; Manufacturer PN: CC0402KRX7R7BB104; Option: I; Package type: SMT; Part Number: C111042XK62YG1; Part Type: 陶瓷电容; ROHS: Y; Remark: Reserved; Status: 商业级; Datasheet: D:\lib\Datasheet\RC\YAGEO-C.pdf
CON1 = J0191113011HR1: CNT single RJ45+LED*2, 16pin/DIP, L/GREEN+R/YELLOW, LED DOWN,  Integrated Magnetics, 10/100/1000BASE-TX, Unknown ROHS; Component Name: CNT single RJ45+LED*2, 16pin/DIP, L/GREEN+R/YELLOW, LED DOWN,  Integrated Magnetics, 10/100/1000BASE-TX, Unknown ROHS    HanRun/HR911130C; Manufacturer: HanRun; Manufacturer PN: HR911130A; Option: I; Package type: DIP; Part Type: 接插件    RJ45; ROHS: /; Remark: 0; Status: U; Datasheet: D:\Program Files\Cadence\lib\Datasheet\connector\01\J0191113011HR1.pdf
D7-D14 = ESD_DIODE_0: ESD Protection devices,ESDPSA-0402/SMT,ESD protection for high speed data lines,ROHS; Component Name: KUU KESD5311N; ID: 160; Manufacturer: KUU; Option: I; Package type: SMT; Part Number: DJ1ESDPSA12SKU-GZ; Part Type: 瞬态电压抑制二极管; ROHS: Y; Remark: Reserved; SIGNAL_MODEL: ESD_DIODE_0_ESDPSA-0402_KESD531; Status: 商业级; Datasheet: D:\lib_ls\Datasheet\KESD5311N.PDF
R75 R95 R97 R99 = R: RESISITOR, 0R Ohm, 1%, R0402/SMT, 1/16W, ROHS; Component Name: 0R 1% R0402 FH RC-02000FT; ID: 1,166; Manufacturer: FH(风华); Manufacturer PN: RC-02000FT; Option: I; Package type: SMT; Part Number: R1100002JC2FH1-GZ; Part Type: 电阻; ROHS: Y; Remark: Dummy; Status: 商业级; Datasheet: D:\lib_ls\Datasheet\RC\FH-R.pdf
R76 R77 R87 R88 R101-R104 = R: RESISITOR, 0R Ohm, 1%, R0402/SMT, 1/16W, ROHS; Component Name: 0R 1% R0402 FH RC-02000FT; ID: 1,166; Manufacturer: FH(风华); Manufacturer PN: RC-02000FT; Option: I; Package type: SMT; Part Number: R1100002JC2FH1-GZ; Part Type: 电阻; ROHS: Y; Remark: Reserved; Status: 商业级; Datasheet: D:\lib_ls\Datasheet\RC\FH-R.pdf
R83-R86 = R: RESISITOR, 84.5R Ohm, 0.1%, R0603/SMT, 1/10W, ROHS; Component Name: 84.5R 0.1% R0603 YAGEO RT0603BRD0784R5L; ID: 1,294; Manufacturer: YAGEO; Manufacturer PN: RT0603BRD0784R5L; NEW_DESCRIPTION: RESISITOR, 178R Ohm,0.1%,R0603/SMT, 1/10W,ROHS; Option: I; Package type: SMT; Part Number: R1184R53FC2YG1-GZ; Part Type: 电阻; ROHS: Y; Remark: Reserved; Status: 商业级; VENDOR: YAGEO; VENDOR_PART_NO: RT0603BRD07178RL; Datasheet: D:\lib_ls\Datasheet\RC\YAGEO-R.pdf
R94 R96 R98 R100 R183-R186 = R: RESISITOR, 0R Ohm, 1%, R0402/SMT, 1/16W, ROHS; Component Name: 0R 1% R0402 FH RC-02000FT; ID: 1,166; Manufacturer: FH(风华); Manufacturer PN: RC-02000FT; NEW_DESCRIPTION: RESISITOR, 0R Ohm,1%,R0603/SMT, 1/10W,ROHS; Option: I; Package type: SMT; Part Number: R1100002JC2FH1-GZ; Part Type: 电阻; ROHS: Y; Remark: Reserved; Status: 商业级; VENDOR: UNI-ROYAL; VENDOR_PART_NO: 0603WAF0000T5E; Datasheet: D:\lib_ls\Datasheet\RC\FH-R.pdf
R129 = R: RESISITOR, 1M Ohm, 5%, R0603/SMT, 1/10W, ROHS; Component Name: 1M 5% R0603 TORCH RC0603-105J-T; ID: 29; Manufacturer: TORCH; Manufacturer PN: RC0603-105J-T; Option: I; Package type: SMT; Part Number: R1101053JC2TO1; Part Type: 电阻; ROHS: Y; Remark: Reserved; Status: 商业级; Datasheet: D:\lib_ls\Datasheet\RC\TORCH-R.pdf
R137 R143 = R: RESISITOR, 330R Ohm, 5%, R0402/SMT, 1/16W, ROHS; Component Name: 330R 5% R0402 FH RC-02W331JT; ID: 1,191; Manufacturer: FH(风华); Manufacturer PN: RC-02W331JT; Option: I; Package type: SMT; Part Number: R1103312JC2FH1-GZ; Part Type: 电阻; ROHS: Y; Remark: Reserved; Status: 商业级; Datasheet: D:\lib_ls\Datasheet\RC\FH-R.pdf
R139 = R: RESISITOR, 0R Ohm, 5%, R0402/SMT, 1/16W, ROHS; Component Name: 0R 5% R0402 FH RC-02000JT; ID: 1,250; Manufacturer: FH(风华); Manufacturer PN: RC-02000JT; Option: I; Package type: SMT; Part Number: R1100002JC2FH1-GZ; Part Type: 电阻; ROHS: Y; Remark: Reserved; Status: 商业级; Datasheet: D:\lib_ls\Datasheet\RC\FH-R.pdf
R141 = R: RESISITOR, 0R Ohm, 1%, R0402/SMT, 1/16W, ROHS; Component Name: 0R 1% R0402 FH RC-02000FT; ID: 1,043; Manufacturer: FH(风华); Manufacturer PN: RC-02000FT; Option: I; Package type: SMT; Part Number: R1100002JC2FH1; Part Type: 电阻; ROHS: Y; Remark: Reserved; Status: 商业级; Datasheet: D:\lib_ls\Datasheet\RC\FH-R.pdf
R177-R180 = R: RESISITOR, 84.5R Ohm, 0.1%, R0603/SMT, 1/10W, ROHS; Component Name: 84.5R 0.1% R0603 YAGEO RT0603BRD0784R5L; ID: 1,294; Manufacturer: YAGEO; Manufacturer PN: RT0603BRD0784R5L; NEW_DESCRIPTION: RESISITOR, 178R Ohm,0.1%,R0603/SMT, 1/10W,ROHS; Option: I; Package type: SMT; Part Number: R1184R53FC2YG1-GZ; Part Type: 电阻; ROHS: Y; Remark: Dummy; Status: 商业级; VENDOR: YAGEO; VENDOR_PART_NO: RT0603BRD07178RL; Datasheet: D:\lib_ls\Datasheet\RC\YAGEO-R.pdf
U5 = RS6334: IC CMOS OP Amplifiers,RUNIC/RS6334XTQC16,TQFN3x3-16L/SMT,FOUR Amplifier,5.6V, GAIN BAND WIDTH 1MHz, ROHS; Component Name: RUNIC RS6334XTQC16; ID: 1,108; Manufacturer: RUNIC(润石); Manufacturer PN: RS6334XTQC16; Option: I; Part Number: UZ1RS6334XTRI1-GZ; Part Type: IC/Amplifiers; ROHS: Y; Remark: Reserved; Status: 工业级; Datasheet: D:\lib_ls\Datasheet\RS6334XTQC16.pdf
C32 = C: CAP,MLCC,0.1UF,50V,10%,C0603/SMT,X7R,ROHS; Component Name: 0.1UF 50V C0603 YAGEO C0603KRX7R9BB104; ID: 24; Manufacturer: YAGEO; Manufacturer PN: C0603KRX7R9BB104; Option: I; Package type: SMT; Part: 0.1UF 16V; Part Number: C111043XKA2YG1; Part Type: 陶瓷电容; ROHS: Y; Remark: Reserved; Status: 商业级; Datasheet: D:\lib_ls\Datasheet\RC\YAGEO-C.pdf
C33 C34 C63-C66 C75 = C: CAP,MLCC,47UF,6.3V,20%,C0805/SMT,X5R,ROHS; Component Name: 47UF 6.3V C0805 YAGEO CC0805MKX5R5BB476; Manufacturer: YAGEO; Manufacturer PN: CC0805MKX5R5BB476; Part Number: C1147645M42YG1; Part Type: 陶瓷电容; ROHS: Y; Status: 商业级; Temperature: Ta=﹣55 to 85; Datasheet: D:\lib_ls\Datasheet\RC\YAGEO-C.pdf
C36 = C: CAP,MLCC,10PF,50V,5%,C0402/SMT,NPO,ROHS; Component Name: 10PF 50V C0402 YAGEO C0402JRNPO9BN100; ID: 2; Manufacturer: YAGEO; Manufacturer PN: C0402JRNPO9BN100; Option: I; Package type: SMT; Part Number: C111002NJA2YG1; Part Type: 陶瓷电容; ROHS: Y; Remark: Reserved; Status: 商业级; Datasheet: Z:\lib\Datasheet\RC\YAGEO-C.pdf
C79 = C: CAP,MLCC,2.2UF,16V,10%,C0603/SMT,X5R,ROHS; Component Name: 2.2UF 16V C0603 YAGEO CC0603KRX5R7BB225; ID: 89; Manufacturer: YAGEO; Manufacturer PN: CC0603KRX5R7BB225; Option: I; Package type: SMT; Part Number: C1122535K62YG1; Part Type: 陶瓷电容; ROHS: Y; Remark: Reserved; Status: 商业级; Datasheet: Z:\lib\Datasheet\RC\YAGEO-C.pdf
C80 = C: CAP，MLCC,10uF,10V,10%,C0603/SMT,X5R,ROHS; Component Name: 10UF 10V C0603 CC0603KRX5R6BB106; Manufacturer: YAGEO; Manufacturer PN: CC0603KRX5R6BB106; Option: I; Part Number: C1110635K52YG1; Part Type: 陶瓷电容; ROHS: Y; Remark: Reserved; Status: 商业级
D15 = LED_0: LED BLUE,LED0603/SMT,Vr=5V,If=5mA,ROHS; Component Name: EVERLIGHT LED Red 17_21SURC/S530-A3/TR8; ID: 45; Manufacturer: 国星光电; Manufacturer PN: NCD0603B1; Option: I; Package type: SMT; Part Type: LED蓝灯色; ROHS: Y; Remark: Reserved; Status: 商业级; Datasheet: D:\lib_ls\Datasheet\Diodes-Transistor\17_21SURC_S530-A3_TR8.pdf
FB8 = BEAD: IND FERRITE BEAD, 60 Ohm, ±25%, FB0603/SMT, 3A, 0.04 Ohm, ROHS; Component Name: 60@100MHZ 3A PBY160808T-600Y-N; Manufacturer: CHILISIN; Manufacturer PN: PBY160808T-600Y-N; Option: I; Package type: SMT; Part Number: LFB60031YF2CN1; Part Type: 磁珠; ROHS: Y; Remark: Dummy; Status: 商业级; Datasheet: D:\lib\Datasheet\Inductor-Bead\PBY160808T-600Y-N.pdf
L1 = INDUCTOR: IND, 1.5UH, ±20%, PL0504/SMT, 6A, 4.60mOhm,ROHS; Component Name: 1.5UH 6A FXL0420-1R5-M; ID: 133; Manufacturer: cjiang(长江微电); Manufacturer PN: FXL0420-1R5-M; Option: I; Package type: SMT; Part Number: L221R5Z1MN3CJ1-GZ; Part Type: 电感; ROHS: Y; Remark: Reserved; Status: 商业级; Datasheet: D:\lib_ls\Datasheet\Inductor-Bead\CJING-L.pdf
MK1-MK8 = MARK: Mark Point; Component Name: Mark Point; Manufacturer: N/A; Manufacturer PN: N/A; Option: NI; Package type: SMT; Part Number: NMP00001; Part Type: NO PN; Remark: Dummy; Status: U
R63 = R_v5: RESISITOR, 1K Ohm, 5%, R0402/SMT, 1/16W, ROHS; Component Name: 1K 5% R0402 YAGEO RC0402JR-071KL; ID: 18; Manufacturer: YAGEO; Manufacturer PN: RC0402JR-071KL; Option: I; Package type: SMT; Part Number: R1101022JC2YG1; Part Type: 电阻; ROHS: Y; Remark: Reserved; Status: 商业级; Datasheet: D:\lib_ls\Datasheet\RC\YAGEO-R.pdf
R105 = R_v5: RESISITOR, 3.9K Ohm, 1%, R0402/SMT, 1/16W, ROHS; Component Name: 3.9K 1% R0402 YAGEO RC0402FR-073K9L; ID: 435; Manufacturer: YAGEO; Manufacturer PN: RC0402FR-073K9L; Option: I; Package type: SMT; Part Number: R1139012FC2YG1; Part Type: 电阻; ROHS: Y; Remark: Reserved; Status: 商业级; Datasheet: D:\lib_ls\Datasheet\RC\YAGEO-R.pdf
R108 = R_v5: RESISITOR, 17.8K Ohm, 1%, R0402/SMT, 1/16W, ROHS; Component Name: 17.8K 1% R0402 FH RC-02W1782FT; ID: 1,177; Manufacturer: FH(风华); Manufacturer PN: RC-02W1782FT; Option: I; Package type: SMT; Part Number: R1117822FC2FH1-GZ; Part Type: 电阻; ROHS: Y; Remark: Reserved; Status: 商业级; Datasheet: D:\lib_ls\Datasheet\RC\FH-R.pdf
R109 = R_v5: RESISITOR, 80.6K Ohm, 1%, R0402/SMT, 1/16W, ROHS; Component Name: 80.6K 1% R0402 FH RC-02K8062FT; ID: 1,215; Manufacturer: FH(风华); Manufacturer PN: RC-02K8062FT; Option: I; Package type: SMT; Part Number: R1180622FC2FH1-GZ; Part Type: 电阻; ROHS: Y; Remark: Reserved; Status: 商业级; Datasheet: D:\lib_ls\Datasheet\RC\FH-R.pdf
R110 = R_v5: RESISITOR, 16K Ohm, 1%, R0402/SMT, 1/16W, ROHS; Component Name: 16K 1% R0402 YAGEO RC0402FR-0716K; ID: 275; Manufacturer: YAGEO; Manufacturer PN: RC0402FR-0716K; Option: I; Package type: SMT; Part Number: R1116022FC2YG1; Part Type: 电阻; ROHS: Y; Remark: Reserved; Status: 商业级; Datasheet: D:\lib_ls\Datasheet\RC\YAGEO-R.pdf
R164 = R_v5: RESISITOR, 3.4K Ohm, 1%, R0402/SMT, 1/16W, ROHS; Component Name: 3.4K 1% R0402 YAGEO RC0402FR-073K4L; ID: 414; Manufacturer: YAGEO; Manufacturer PN: RC0402FR-073K4L; Option: I; Package type: SMT; Part Number: R1134012FC2YG1; Part Type: 电阻; ROHS: Y; Remark: Reserved; Status: 商业级; Datasheet: D:\lib_ls\Datasheet\RC\YAGEO-R.pdf
R212 = R_v5: RESISTOR, 100K Ohm, 1%, R0402/SMT, 1/16W, ROHS; Component Name: 100K 1% R0402 YAGEO RC0402FR-07100KL; ID: 193; Manufacturer: YAGEO; Manufacturer PN: RC0402FR-07100KL; Option: I; Part Number: R1110032FC2YG1; Part Type: 电阻; ROHS: Y; Remark: Dummy; Status: 商业级; Datasheet: D:\lib_ls\Datasheet\RC\YAGEO-R.pdf
TP4 TP10 = SD_TSTR: PAGE: 5; Remark: Dummy
U7 = JW5079A: IC POWER, JOULWATT/JW5079AQFNF#TRPBF, QFN3X3_20/SMT,10A,23V,500KHZ STEP-DOWN CONVERTER, ROHS; Component Name: JOULWATT JW5079A; ID: 1,072; Manufacturer: Joulwatt(杰华特); Manufacturer PN: JW5079AQFNF#TRPBF; Option: I; Part Number: UP1JW5079H2JW1-GZ; Part Type: IC/POWER; ROHS: Y; Remark: Reserved; Status: 商业级; Datasheet: D:\lib_ls\Datasheet\IC\JW5079A.pdf
U9 = SY6280: IC LOAD SWITCH,SILERGY(矽力杰)/SY6280AAC,SOT23-5/SMT,Ultra-Low On-Resistance,2A,Soft Start,2.4V-5.5V,ROHS; Component Name: SY6280AAC; ID: 1,084; Manufacturer: SILERGY(矽力杰); Manufacturer PN: SY6280AAC; Option: I; Package type: SMT; Part Number: UZ1SY6280H2SY1-GZ; Part Type: IC/Others; ROHS: Y; Remark: Reserved; Status: 工业级; Datasheet: D:\lib_ls\Datasheet\SY6280AAC.pdf

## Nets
GND: C3.2 C4.1 C5.1 C7.1 C8.2 C9.2 C11.2 C23.2 C24.2 C25.2 C26.2 C27.1 C28.1 C29.1 C30.1 C31.1 C33.2 C34.2 C35.1 C46.1 C47.1 C60.1 C63.2 C64.2 C65.2 C66.2 C68.1 C69.1 C70.1 C71.1 C72.2 C73.2 C74.1 C75.2 C76.2 C77.1 C78.1 C79.2 C80.2 CON2.4(CON_PIN[14]) CON2.8(CON_PIN[18]) CON5.11 CON5.20 CON5.29 CON5.41 CON5.42 D7.1 D8.1 D9.1 D10.1 D11.1 D12.1 D13.1 D14.1 D15.C(CATHODE) D19.2 D20.2 D21.2 D22.2 D23.2 EC2.2 EC3.2 J8.2 Q2.2(SOURCE) Q5.2(SOURCE) R9.2 R10.2 R83.1 R84.1 R85.1 R86.1 R92.1 R105.2 R107.2 R108.2 R129.2 R139.2 R146.2 R164.1 R177.1 R178.1 R179.1 R180.1 U5.11(V-) U5.17(GND) U6.2(GND) U7.7(GND1) U7.8(GND2) U7.18(GND3) U7.21(GND4) U9.2(GND) ; also on sheet 6 7 8 9 10 13
GND_EARTH_R: C4.2 C47.2 CON1.10 CON1.15 CON1.16 CON2.9(SH1) CON2.10(SH2) CON2.11(SH3) CON2.12(SH4) R129.1 R146.1 ; also on sheet 6
P3V3: C64.1 C65.1 C66.1 C72.1 FB8.2 R12.1 R16.1 R17.1 R21.2 R23.1 R25.1 R29.1 R63.1 R64.1 R65.1 R89.2 R91.2 R143.2 R181.2 R212.2 TP10.1 U9.1(OUT) ; also on sheet 7 9 10 13
P3V3_IN: C33.1 C34.1 C63.1 C75.1 C77.2 C78.2 FB8.1 L1.2 R109.2 R168.2 R216.2 TP4.1 U9.5(IN) ; also on sheet 8 10
P3V3_PG: R212.1 U7.9(PG)
P3V3EN: C35.2 R105.1 R110.1 U7.11(EN)
P5V: C24.1 C26.1 C29.2 C73.1 C76.1 FB2.1 FB5.1 FB9.1 R80.1 R93.1 R106.2 R110.2 U6.5(IN) U7.2(VIN1) U7.3(VIN2) U7.4(VIN3) U7.5(VIN4) ; also on sheet 6 9
P5V_ADC: C74.2 FB9.2 U5.2(V+)
ADC_IN0: R103.2 U5.15(OUTA) U5.16(-INA)
ADC_IN1: R77.2 U5.4(-INB) U5.5(OUTB)
ADC_IN2: R76.2 U5.8(OUTC) U5.9(-INC)
ADC_IN3: R102.2 U5.13(-IND) U5.14(OUTD)
ADCIN0: C31.2 R86.2 R99.1 R100.1 R104.1
ADCIN0+: R104.2 U5.1(+INA)
ADCIN1: C28.2 R85.2 R88.1 R97.1 R98.1
ADCIN1+: R88.2 U5.3(+INB)
ADCIN2: C27.2 R75.1 R84.2 R87.1 R96.1
ADCIN2+: R87.2 U5.10(+INC)
ADCIN3: C30.2 R83.2 R94.1 R95.1 R101.1
AI0: R100.2 ; also on sheet 9
AI1: R98.2 ; also on sheet 9
AI2: R96.2 ; also on sheet 9
AI3: R94.2 ; also on sheet 9
AI4: R183.2 ; also on sheet 9
AI5: R186.2 ; also on sheet 9
AI6: R185.2 ; also on sheet 9
AI7: R184.2 ; also on sheet 9
CPU_ADC_IN0: R99.2 R103.1 ; also on sheet 8
CPU_ADC_IN1: R77.1 R97.2 ; also on sheet 8
CPU_ADC_IN2: R75.2 R76.1 ; also on sheet 8
CPU_ADC_IN3: R95.2 R102.1 ; also on sheet 8
CPU_ADC_IN4: C68.2 R177.2 R183.1 ; also on sheet 8
CPU_ADC_IN5: C71.2 R180.2 R186.1 ; also on sheet 8
CPU_ADC_IN6: C70.2 R179.2 R185.1 ; also on sheet 8
CPU_ADC_IN7: C69.2 R178.2 R184.1 ; also on sheet 8
CPU_I2C1_SCL: R58.1 R64.2 ; also on sheet 8 9
CPU_I2C1_SDA: R60.1 R65.2 ; also on sheet 8 9
CPU_LCD_CLK: FB1.1 ; also on sheet 8
CPU_LCD_DATA0: R13.1 ; also on sheet 8
CPU_LCD_DATA1: R12.2 R36.1 ; also on sheet 8
CPU_LCD_DATA2: R10.1 R11.1 ; also on sheet 8
CPU_LCD_DATA3: R9.1 R34.1 ; also on sheet 8
CPU_LCD_DATA4: R23.2 R32.1 ; also on sheet 8
CPU_LCD_DATA5: R25.2 R27.1 ; also on sheet 8
CPU_LCD_DATA6: R30.1 ; also on sheet 8
CPU_LCD_DATA7: R28.1 R29.2 ; also on sheet 8
CPU_LCD_DATA8: R40.1 ; also on sheet 8
CPU_LCD_DATA9: R145.1 ; also on sheet 8
CPU_LCD_DATA10: R31.1 ; also on sheet 8
CPU_LCD_DATA11: R33.1 ; also on sheet 8
CPU_LCD_DATA12: R35.1 ; also on sheet 8
CPU_LCD_DATA13: R37.1 ; also on sheet 8
CPU_LCD_DATA14: R39.1 ; also on sheet 8
CPU_LCD_DATA15: R38.1 ; also on sheet 8
CPU_LCD_DATA16: R41.1 ; also on sheet 8
CPU_LCD_DATA17: R43.1 ; also on sheet 8
CPU_LCD_DATA18: R45.1 ; also on sheet 8
CPU_LCD_DATA19: R50.1 ; also on sheet 8
CPU_LCD_DATA20: R48.1 ; also on sheet 8
CPU_LCD_DATA21: R46.1 ; also on sheet 8
CPU_LCD_DATA22: R44.1 ; also on sheet 8
CPU_LCD_DATA23: R42.1 ; also on sheet 8
CPU_LCD_EN: R14.1 ; also on sheet 8
CPU_LCD_HSYNC: R26.1 ; also on sheet 8
CPU_LCD_VSYNC: R15.1 ; also on sheet 8
CPU_SPI2_CLK: R8.1 ; also on sheet 8 9
CPU_SPI2_CSN: R22.1 ; also on sheet 8 9
CPU_SPI2_MISO: R18.1 ; also on sheet 8 9
CPU_SPI2_MOSI: R19.1 ; also on sheet 8 9
CPU_TIM1_CH1N: R16.2 R24.2 ; also on sheet 8
CPU_TIM1_CH2: R6.2 R17.2 ; also on sheet 8
CPU_USB0_DM: CHK1.2 R68.2 ; also on sheet 8
CPU_USB0_DP: CHK1.1 R66.2 ; also on sheet 8
CPU_USB0_DRVBUS: R82.1 R89.1 R90.1 ; also on sheet 8
CPU_USB0_ID: D23.1 J8.1 ; also on sheet 8
CPU_USB1_DM: CHK2.2 R70.2 ; also on sheet 8
CPU_USB1_DP: CHK2.1 R69.2 ; also on sheet 8
CPU_USB1_OC: Q5.3(DRAIN) R181.1 ; also on sheet 8
GPIO82: CON5.39 R6.1
GPIO84: CON5.34 R24.1
LCD_B0: CON5.21 R13.2
LCD_B1: CON5.22 R36.2
LCD_B2: CON5.23 R11.2
LCD_B3: CON5.24 R34.2
LCD_B4: CON5.25 R32.2
LCD_B5: CON5.26 R27.2
LCD_B6: CON5.27 R30.2
LCD_B7: CON5.28 R28.2
LCD_CLK: C3.1 CON5.30 FB1.2
LCD_DE: CON5.33 R14.2
LCD_G0: CON5.12 R40.2
LCD_G1: CON5.13 R145.2
LCD_G2: CON5.14 R31.2
LCD_G3: CON5.15 R33.2
LCD_G4: CON5.16 R35.2
LCD_G5: CON5.17 R37.2
LCD_G6: CON5.18 R39.2
LCD_G7: CON5.19 R38.2
LCD_HSYNC: CON5.31 R26.2
LCD_R0: CON5.3 R41.2
LCD_R1: CON5.4 R43.2
LCD_R2: CON5.5 R45.2
LCD_R3: CON5.6 R50.2
LCD_R4: CON5.7 R48.2
LCD_R5: CON5.8 R46.2
LCD_R6: CON5.9 R44.2
LCD_R7: CON5.10 R42.2
LCD_RESETn: D17.A(ANODE) R7.1 R20.1
LCD_VSYNC: CON5.32 R15.2
MB_PWREN: R157.1 ; also on sheet 8
P0_MDIO0+: CON1.2 D14.2 ; also on sheet 8
P0_MDIO0-: CON1.3 D13.2 ; also on sheet 8
P0_MDIO1+: CON1.4 D12.2 ; also on sheet 8
P0_MDIO1-: CON1.7 D11.2 ; also on sheet 8
P0_MDIO2+: CON1.5 D10.2 ; also on sheet 8
P0_MDIO2-: CON1.6 D9.2 ; also on sheet 8
P0_MDIO3+: CON1.8 D8.2 ; also on sheet 8
P0_MDIO3-: CON1.9 D7.2 ; also on sheet 8
PHY0_LED0: C46.2 R141.2 ; also on sheet 8
PHY0_LED1: C5.2 D5.A(ANODE) ; also on sheet 8
PHY0_LED2: C7.2 D6.A(ANODE) ; also on sheet 8
PLTRESETN: D17.C(CATHODE) ; also on sheet 8
T_CS/CT_RST: CON5.35 R20.2 R21.1 R22.2
T_MOSI/CT_SDA: CON5.36 R19.2 R60.2
T_SCL/CT_SCL: CON5.38 R8.2 R58.2
USB0_DM: CHK1.3 CON2.6(CON_PIN[16]) D20.1 R68.1
USB0_DP: CHK1.4 CON2.7(CON_PIN[17]) D19.1 R66.1
USB1_DM: CHK2.3 CON2.2(CON_PIN[12]) D22.1 R70.1
USB1_DP: CHK2.4 CON2.3(CON_PIN[13]) D21.1 R69.1
USB_PWR1: C23.1 CON2.5(CON_PIN[15]) EC2.1 U6.1(VOUT)
USB_PWR2: C25.1 CON2.1(CON_PIN[11]) EC3.1 FB5.2 R81.1
USB_VBUSIN: R80.2 ; also on sheet 8
N21480035: R106.1 R107.1 U7.13(ILMT)
N21480077: C79.1 U7.17(VCC)
N21480090: C32.2 L1.1 U7.6(SW1) U7.19(SW2) U7.20(SW3)
N21480094: C32.1 U7.1(BST)
N21480120: C80.1 U7.15(BYP)
N21480193: C36.1 R108.1 R109.1 U7.14(FB)
N21480303: D15.A(ANODE) R63.2
N21480386: R164.2 U9.3(ISET)
N21480402: C60.2 R157.2 R168.1 U9.4(EN)
N21480619: C36.2 R216.1
N21758418: C8.1 CON1.1
N21758422: CON1.11 R143.1
N21758424: CON1.12 R141.1
N21758431: D5.C(CATHODE) D6.C(CATHODE) R137.2
N21758441: CON1.14 R137.1
N21758443: CON1.13 R139.1
N21838330: C9.1 C11.1 CON5.1 CON5.2 FB2.2
N21838391: CON5.40 R7.2
N21838396: CON5.37 R18.2
N21940880: Q5.1(GATE) R81.2
N21942133: R91.1 U6.3(FAULT#)
N21942139: Q2.3(DRAIN) R90.2 R92.2 R93.2 U6.4(EN)
N21942279: Q2.1(GATE) R82.2
N22007036: R101.2 U5.12(+IND)

Not connected (* = marked no-connect by the designer): MK1 1(ID-BOARD)*; MK2 1(ID-BOARD)*; MK3 1(ID-BOARD)*; MK4 1(ID-BOARD)*; MK5 1(ID-BOARD)*; MK6 1(ID-BOARD)*; MK7 1(ID-BOARD)*; MK8 1(ID-BOARD)*; U5 6(NC1)* 7(NC2)*; U7 10(NC1)* 12(NC2)* 16(NC3)*

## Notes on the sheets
sheet 1
- LCD PORT
sheet 2
- P3V3
- Ilim (A)=6800 / Rset (ohm)
- Ilim (A)=2A
sheet 3
- USB
- HOST --> H
  OTG   --> L
sheet 4
- AI
- LAN
- +
- GREEN
- -
- +
- YELLOW
- -
sheet 5
- GBKPAW0
- CONTENT
- SHEET
- COVER SHEET
- 1
- Version:1.1
- BLOCK DIAGRAM
- 2
- POWER DIAGRAM
- 3
- CORE BOARD CON
- 4
- USB
- 5
- KEY&LED&RESET
- 6
- LCD PORT
- 7
- EJTAG&RTC&TF
- 8
- AI&LAN
- 9
- PIN EXTERNAL
- 10
- USB2UART0
- 11
- DCINV&P5V
- 12
- P3V3
- 13
- REVISION HISTORY
- 14
